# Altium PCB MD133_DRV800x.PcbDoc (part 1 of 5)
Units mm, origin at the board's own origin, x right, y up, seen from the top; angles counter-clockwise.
Board outline 152.66 x 101.89 mm, 4 copper layers (Top Layer, Mid-Layer 1, Mid-Layer 2, Bottom Layer), stack 2.355 mm thick; 306 components, 166 nets, 1010 pads, 1623 vias.
Unrouted connection lines stored in the file: 4.
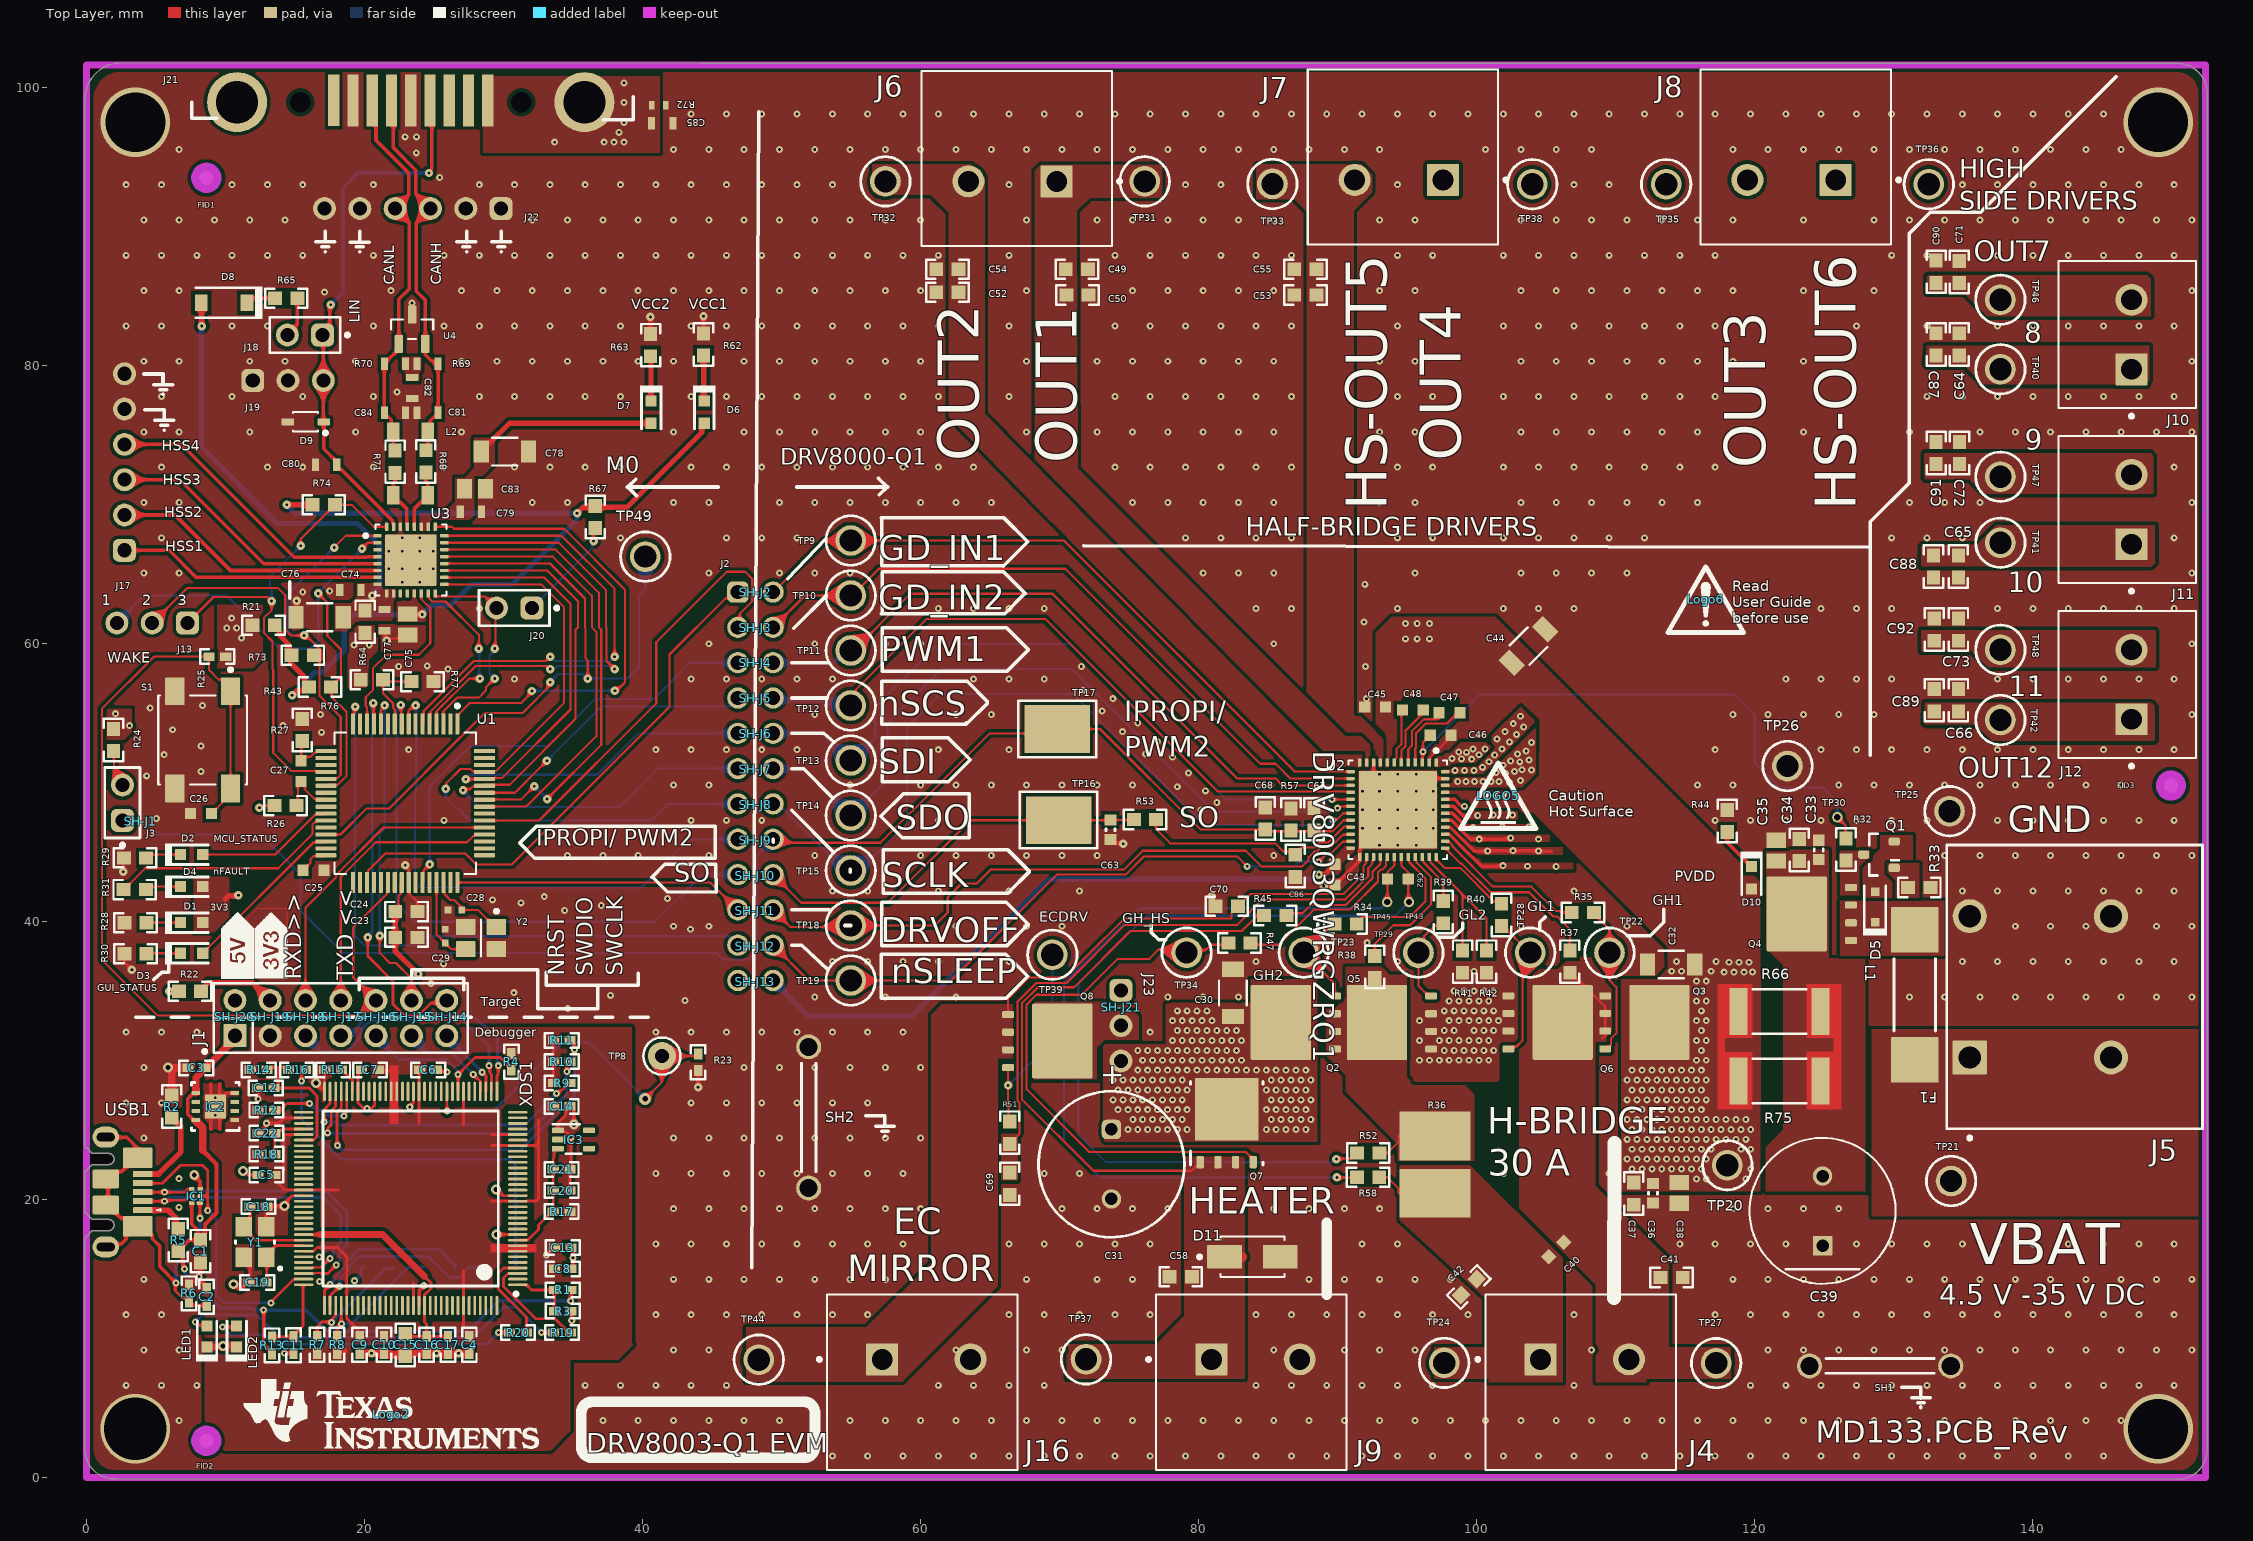
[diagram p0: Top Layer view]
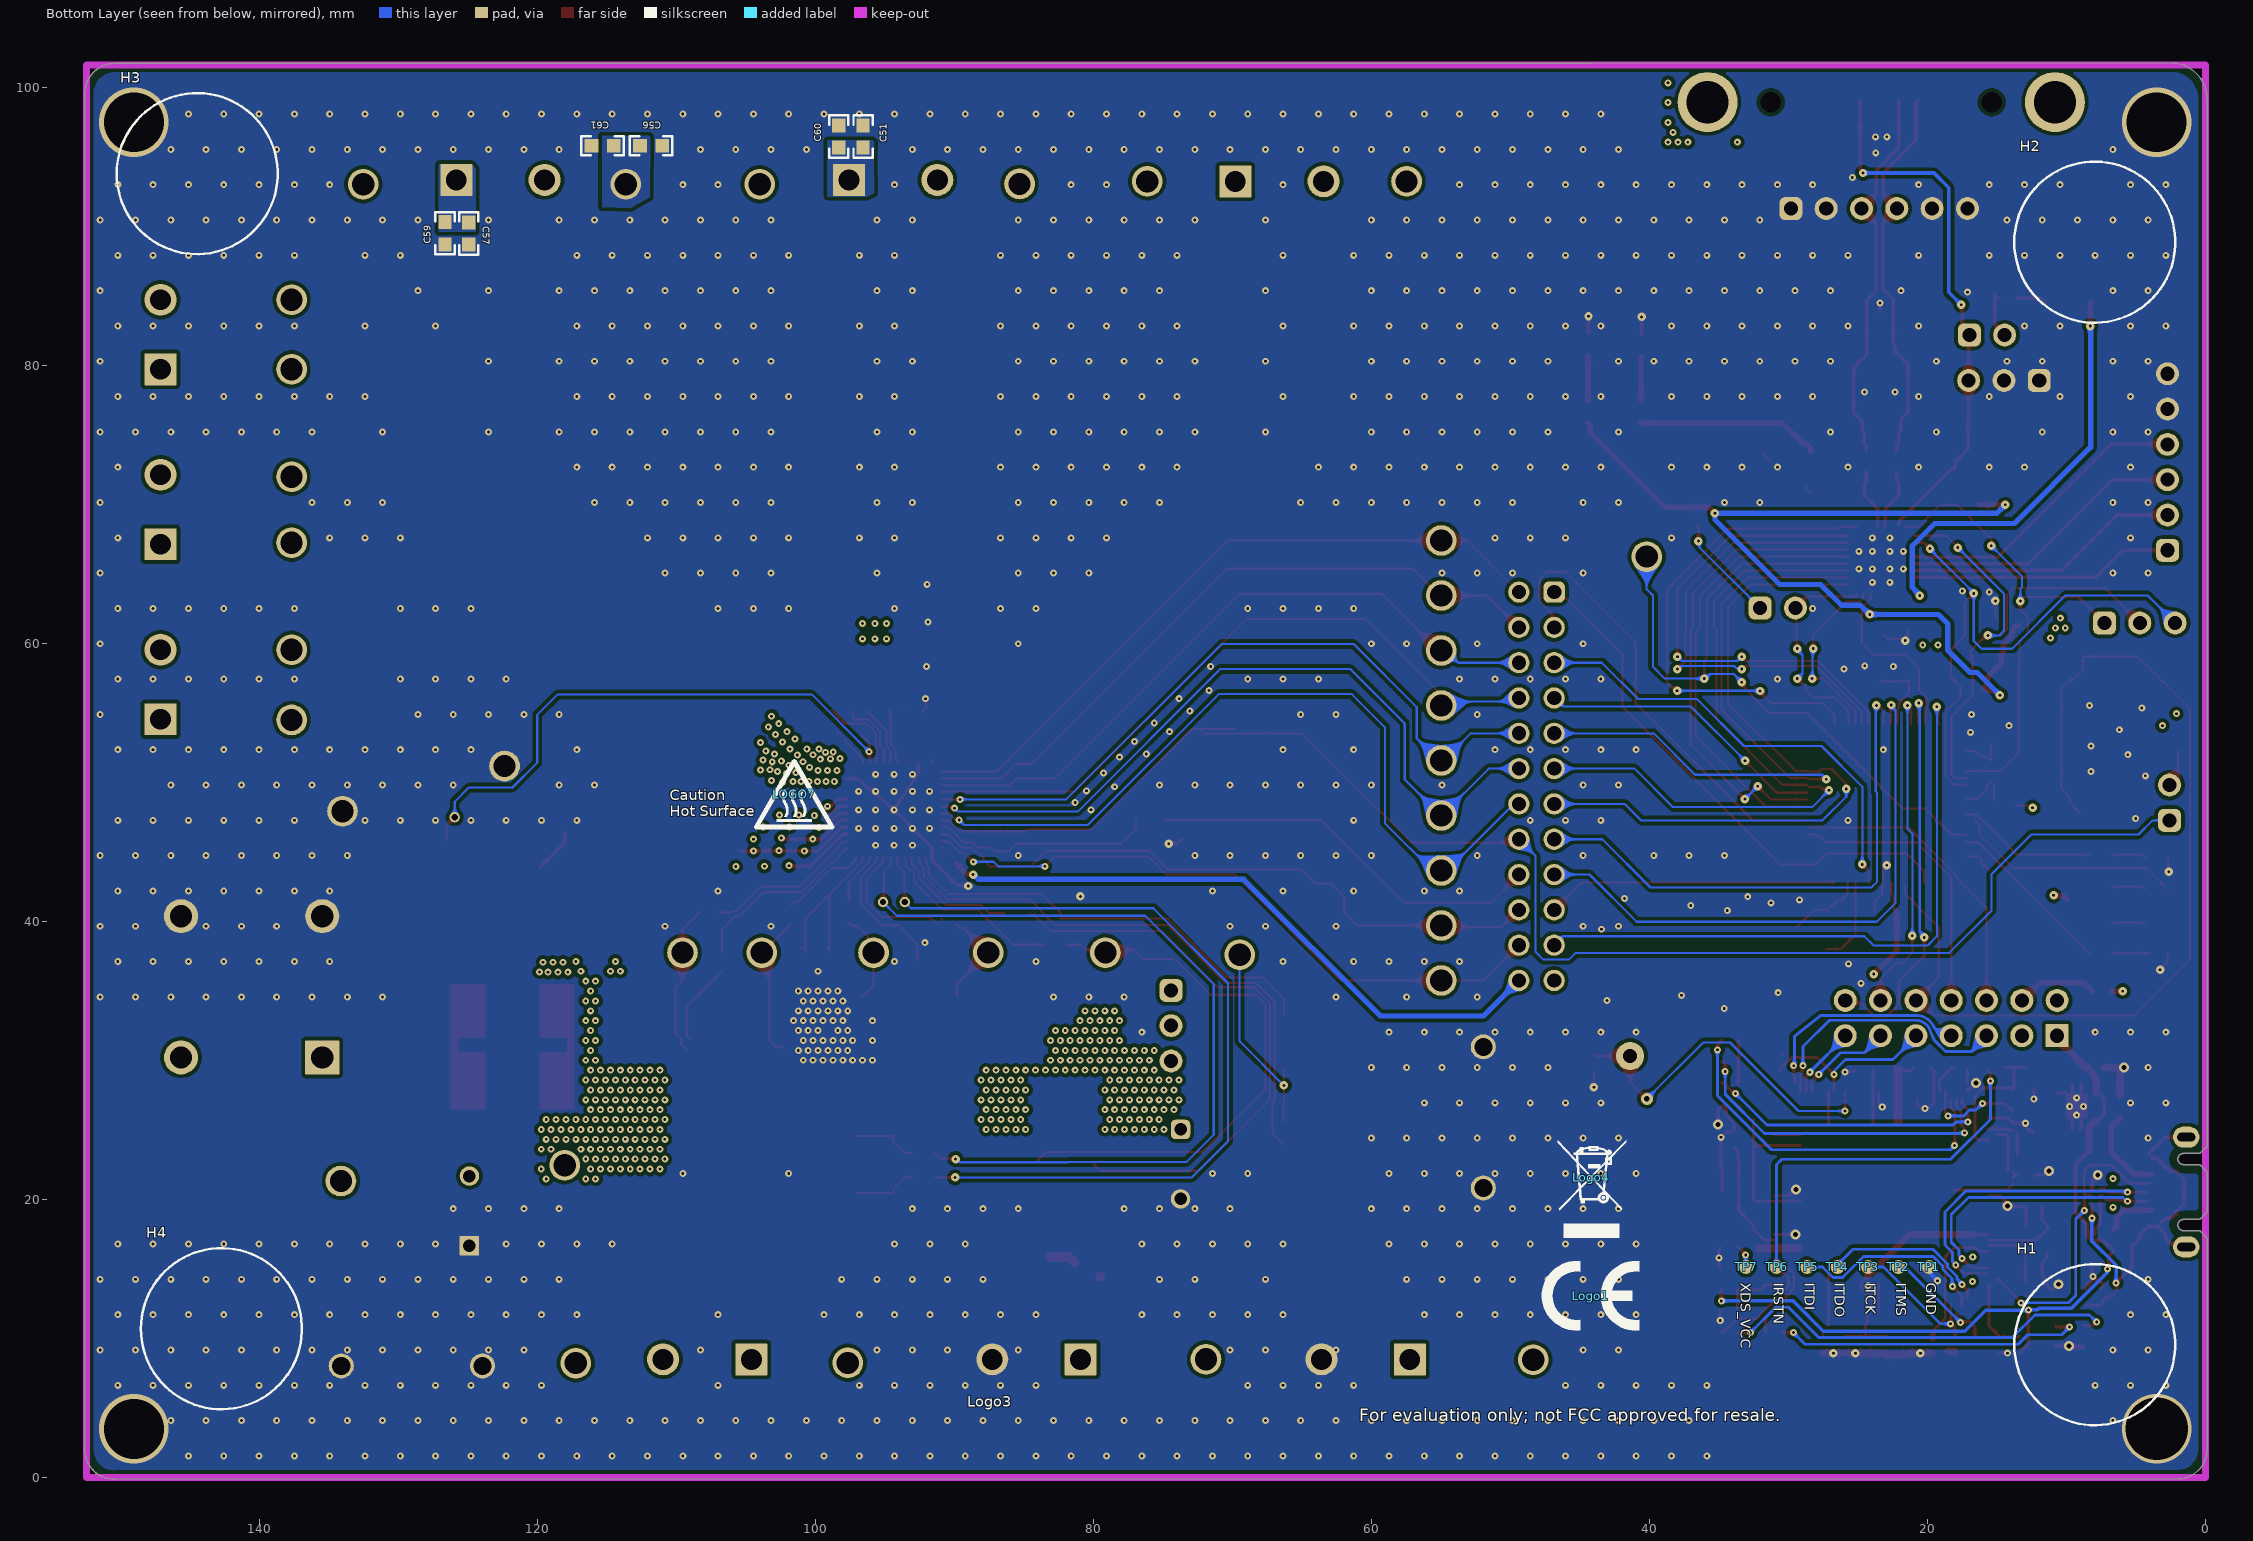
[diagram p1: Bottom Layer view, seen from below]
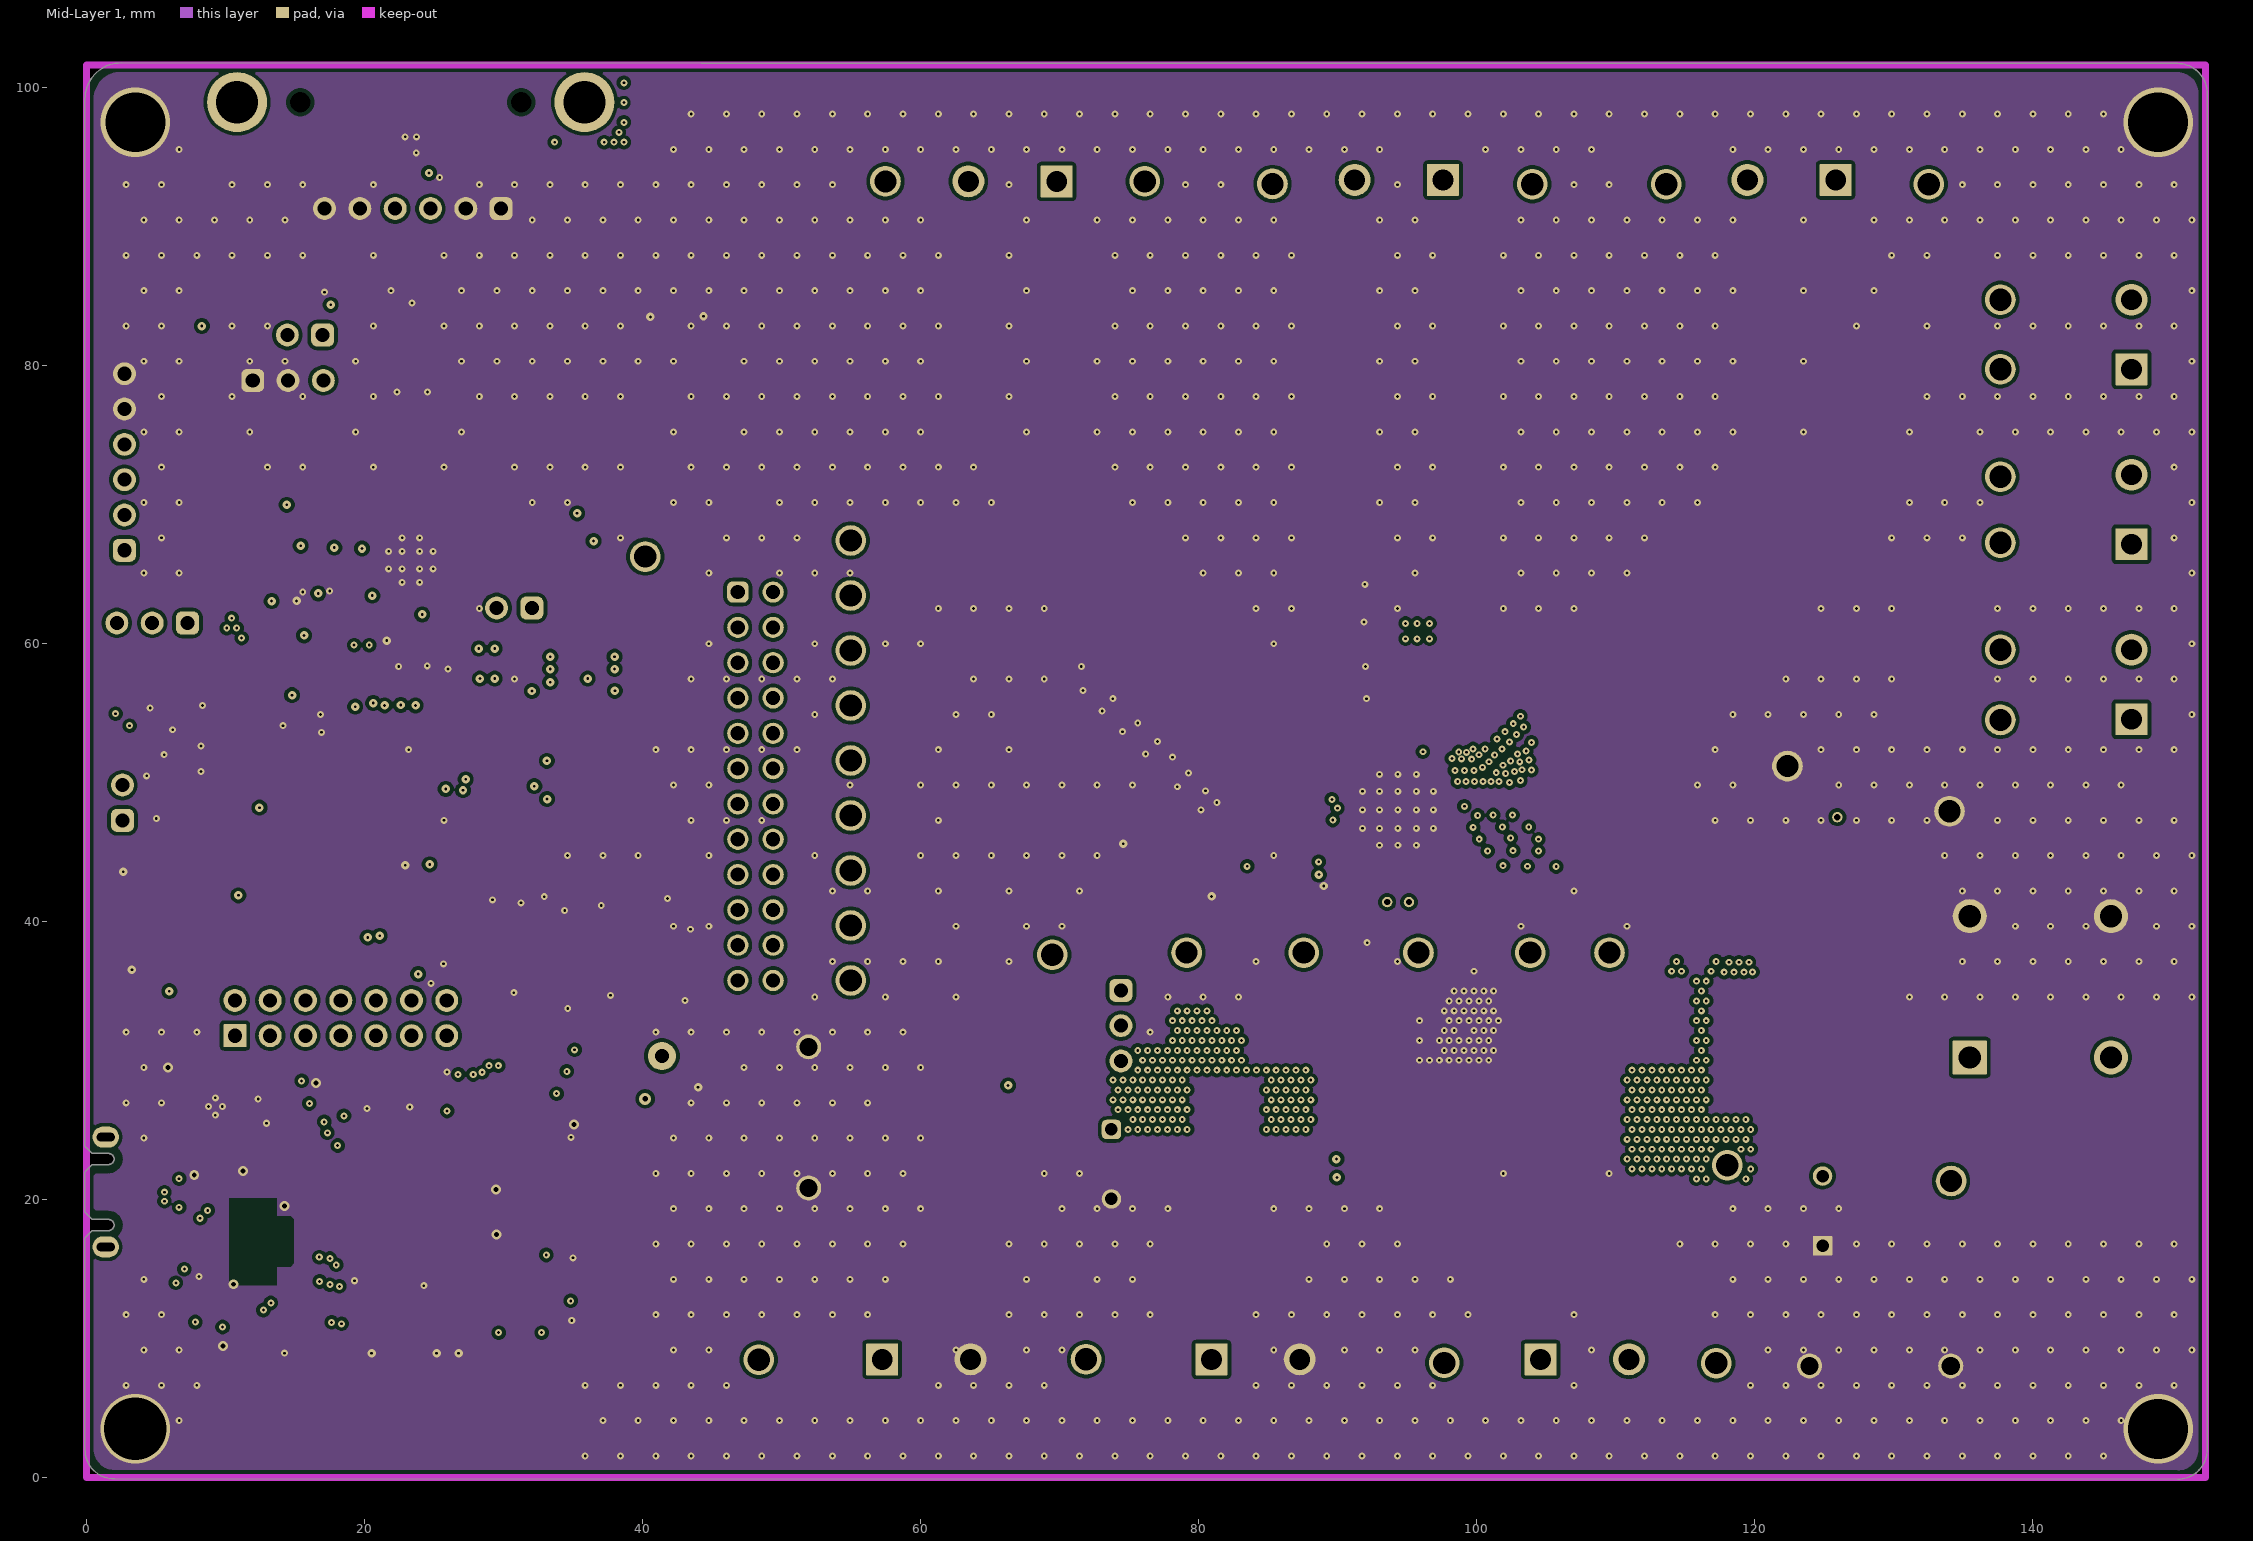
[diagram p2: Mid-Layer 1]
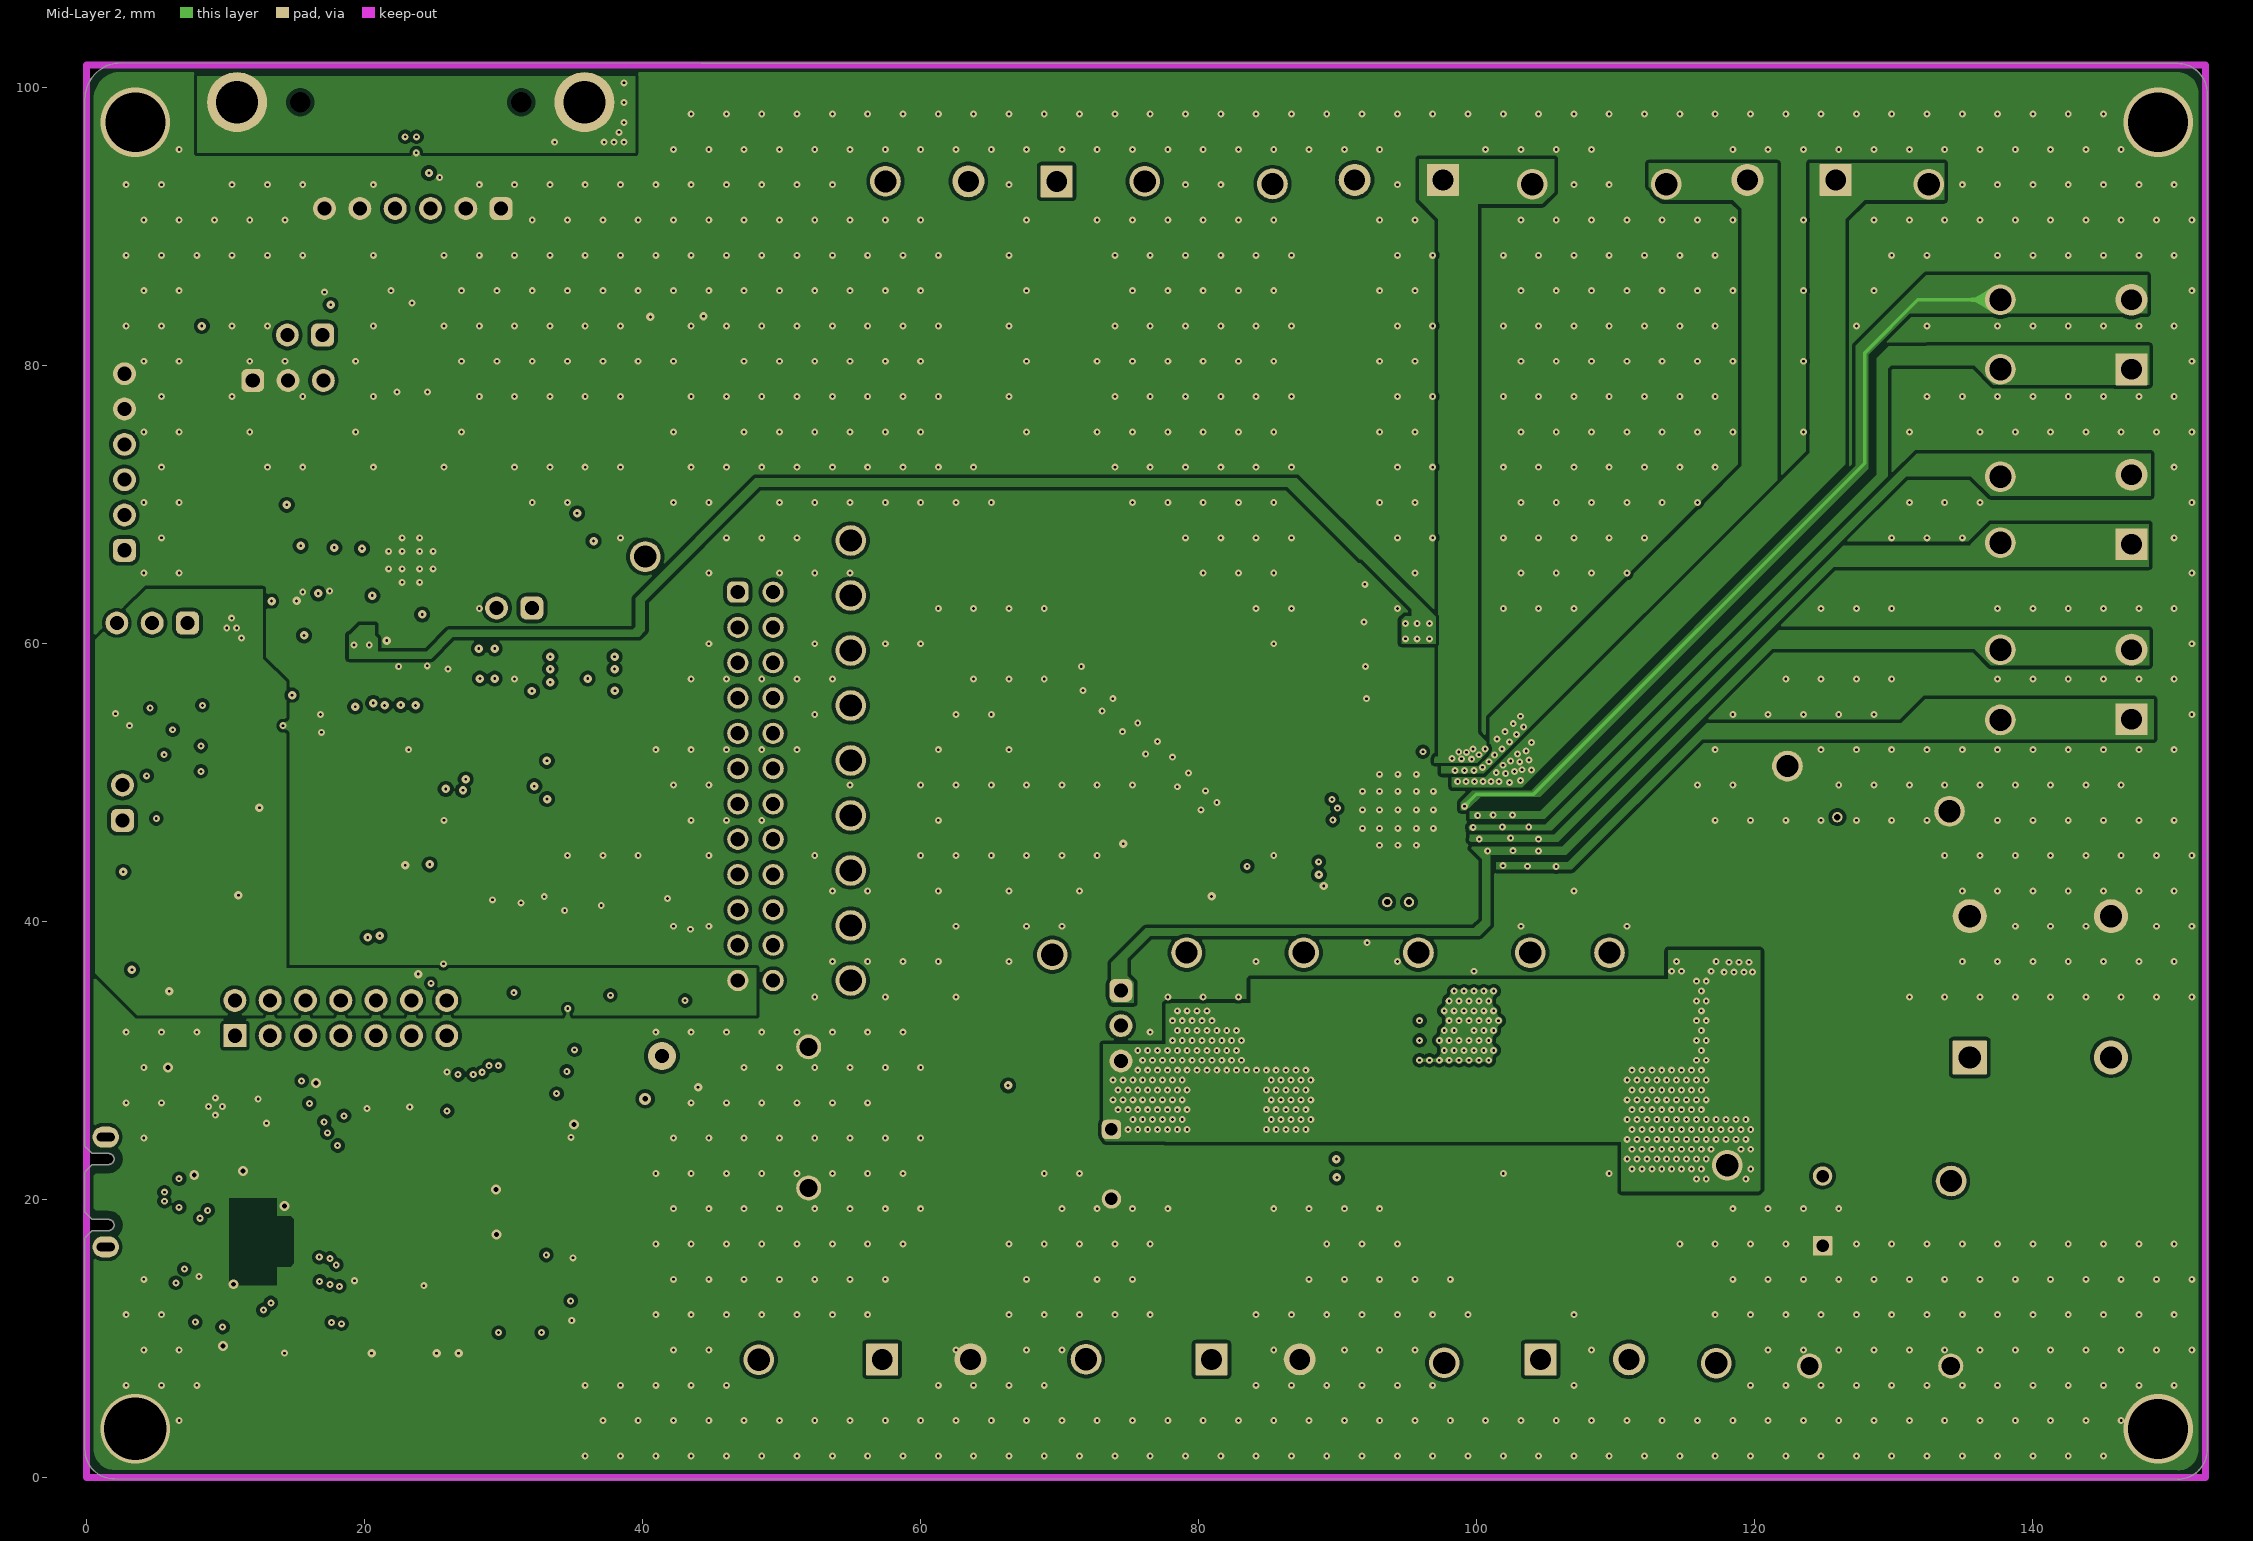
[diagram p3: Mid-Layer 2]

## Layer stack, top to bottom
Top Solder: solder mask 0.0102, Solder Resist, Dk 3.5
Top Layer: signal copper 0.07
Dielectric1: core 1.5037, FR-4 High Tg, Dk 4.8
Mid-Layer 1: signal copper 0.0356
Dielectric2: dielectric 0.32, FR-4, Dk 4.8
Mid-Layer 2: signal copper 0.0356
Dielectric3: dielectric 0.32, FR-4, Dk 4.8
Bottom Layer: signal copper 0.07
Bottom Solder: solder mask 0.0102, Solder Resist, Dk 3.5

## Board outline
-0.127,2.032 -0.127,15.278 -0.13,15.295 -0.13,17.22 -0.116,17.256 0.384,17.756 0.42,17.77 1.57,17.77 ccw(c1.57,18.17) 1.97,18.17 ccw(c1.57,18.17) 1.57,18.57 0.42,18.57 0.384,18.584 -0.116,19.084 -0.13,19.12 -0.13,21.97 -0.116,22.006 0.384,22.506 0.42,22.52 1.57,22.52 ccw(c1.57,22.92) 1.97,22.92 ccw(c1.57,22.92) 1.57,23.32 0.42,23.32 0.384,23.334 -0.009,23.728 cw(c0,23.855) -0.127,23.853 -0.13,23.87 -0.13,25.795 -0.127,25.812 -0.127,91.1 -0.127,99.168 cw(c2.471,99.168) 2.471,101.766 44.195,101.727 150.4,101.727 cw(c150.4,99.6) 152.527,99.6 152.527,2 cw(c150.4,2) 150.4,-0.127 2,-0.095 cw(c2,2.032)

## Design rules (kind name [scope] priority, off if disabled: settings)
AcuteAngle [All] p1: minimum=4.50000000000000E+0001 checktracksonly=FALSE
AssemblyTestPointUsage [All] p1: valid=2
BoardOutlineClearance BoardOutlineClearance_MountingHoles [OnCopper and InComponentClass('Mounting Holes')] p1: gap=0.381 ignorepadtopadclearanceinfootprint=FALSE
BoardOutlineClearance BoardOutlineClearance_Poly [OnCopper and IsPoly] p2: gap=0.635 ignorepadtopadclearanceinfootprint=FALSE
BoardOutlineClearance [OnCopper and Not InComponentClass('Logo') and not InComponentClass('FiducialMark') and not InRegion(1000,500,4000,800) and not InPoly] p3: gap=0.381 ignorepadtopadclearanceinfootprint=FALSE
Clearance Clearance_Keepouts [((IsTrack Or IsArc) And Not InPoly) And IsFree and IsKeepOut vs ((IsTrack Or IsArc) And Not InPoly) And IsFree and IsKeepOut] p1: gap=0 ignorepadtopadclearanceinfootprint=FALSE
Clearance Clearance_Poly [InPolygon] p2: gap=0.254 ignorepadtopadclearanceinfootprint=TRUE
Clearance Clearance_FiducialMark [IsKeepOut and InComponentClass('FiducialMark') vs IsPad and InComponentClass('FiducialMark')] p3: gap=0 ignorepadtopadclearanceinfootprint=TRUE
Clearance [All] p4: gap=0.152 ignorepadtopadclearanceinfootprint=TRUE
ComponentClearance ComponentClearance_PI_FILTER_R75 [InComponent('R75') vs InComponent('L1')] p1: gap=0 collisioncheckmode=3 verticalgap=0 showdistances=FALSE
ComponentClearance ComponentClearance_PI_FILTER_R66 [InComponent('R66') vs InComponent('L1')] p2: gap=0 collisioncheckmode=3 verticalgap=0 showdistances=FALSE
ComponentClearance ComponentClearance_CANL_Choke [InComponent('L2') vs InComponent('R71')] p3: gap=0 collisioncheckmode=3 verticalgap=0 showdistances=FALSE
ComponentClearance ComponentClearance_CANH_Choke [InComponent('L2') vs InComponent('R68')] p4: gap=0 collisioncheckmode=3 verticalgap=0 showdistances=FALSE
ComponentClearance ComponentClearance_MountingHoles_FiducialMarks [InComponentClass('Mounting Holes') vs InComponentClass('FiducialMark')] p5: gap=1.27 collisioncheckmode=3 verticalgap=0.254 showdistances=FALSE
ComponentClearance ComponentClearance_Shunt [InComponentClass('Header') vs InComponentClass('Shunt')] p6: gap=0 collisioncheckmode=3 verticalgap=0 showdistances=FALSE
ComponentClearance ComponentClearance_Logo [InComponentClass('Logo')] p7: gap=0.762 collisioncheckmode=3 verticalgap=0.254 showdistances=FALSE
ComponentClearance ComponentClearance_ScrewToNut [(HasFootprint('NY PMS 440 0025 PH')) vs (HasFootprint('Keystone_1902C'))] p8: gap=0.127 collisioncheckmode=3 verticalgap=0.254 showdistances=FALSE
ComponentClearance ComponentClearance_MountingHoles [InComponentClass('Mounting Holes')] p9: gap=2.54 collisioncheckmode=3 verticalgap=2540 showdistances=FALSE
ComponentClearance ComponentClearance_SmallPassives [HasFootprint('0201*') or HasFootprint('0402*') or HasFootprint('0508') or HasFootprint('0603*') or HasFootprint('0612') or HasFootprint('0805*') or HasFootprint('0815*') or HasFootprint('0830*') or HasFootprint('1206*') or HasFootprint('1210*') or HasFootprint('1808*') or HasFootprint('1812*') or HasFootprint('1825*') or HasFootprint('2010*') or HasFootprint('2220*') or HasFootprint('2225*') or HasFootprint('2512*') or HasFootprint('2728*') or HasFootprint('3518*') vs HasFootprint('0201*') or HasFootprint('0402*') or HasFootprint('0508') or HasFootprint('0603*') or HasFootprint('0612') or HasFootprint('0805*') or HasFootprint('0815*') or HasFootprint('0830*') or HasFootprint('1206*') or HasFootprint('1210*') or HasFootprint('1808*') or HasFootprint('1812*') or HasFootprint('1825*') or HasFootprint('2010*') or HasFootprint('2220*') or HasFootprint('2225*') or HasFootprint('2512*') or HasFootprint('2728*') or HasFootprint('3518*')] p10: gap=0.38 collisioncheckmode=3 verticalgap=0.254 showdistances=FALSE
ComponentClearance ComponentClearance_THtoSMT [IsThruComponent vs IsSMTComponent] p11: gap=0.762 collisioncheckmode=3 verticalgap=0.762 showdistances=FALSE
ComponentClearance ComponentClearance_THtoTH [IsThruComponent vs IsThruComponent] p12: gap=0.508 collisioncheckmode=3 verticalgap=0.762 showdistances=FALSE
ComponentClearance [All] p13: gap=0.508 collisioncheckmode=3 verticalgap=0.254 showdistances=FALSE
DiffPairsRouting [All] p1: maxlimit=2.54 minlimit=0.254 mostfreqgap=0.254 toplayer_minwidth=0.152 toplayer_maxwidth=0.381 toplayer_prefwidth=0.254 midlayer1_minwidth=0.152 midlayer1_maxwidth=0.381 midlayer1_prefwidth=0.254 midlayer2_minwidth=0.152 midlayer2_maxwidth=0.381 midlayer2_prefwidth=0.254 bottomlayer_minwidth=0.152 bottomlayer_maxwidth=0.381 bottomlayer_prefwidth=0.254 maxuncoupledlength=25.4
FabricationTestPointUsage TestPointUsage [All] p1: valid=2 allowmultiple=FALSE
FabricationTestpoint Testpoint [All] p1: side=3 testpointundercomponent=TRUE minsize=1.016 maxsize=2.54 preferedsize=1.524 minholesize=0 maxholesize=1.016 preferedholesize=0.813 testpointgrid=0.025 allowsidetop=TRUE allowsidebottom=TRUE usegrid=TRUE gridtolerance=0
FanoutControl Fanout_LCC [IsLCC] p1: bgadir=Out bgaviamode=Centered fanoutstyle=Auto fanoutdirection=Alternating viagrid=0.025 // Fanout_LCC (Default Rule)
FanoutControl Fanout_BGA [IsBGA] p2: bgadir=Out bgaviamode=Centered fanoutstyle=Auto fanoutdirection=Alternating viagrid=0.025 // Fanout_BGA (Default Rule)
FanoutControl Fanout_Default [All] p4: bgadir=Out bgaviamode=Centered fanoutstyle=Auto fanoutdirection=Alternating viagrid=0.025 // Fanout_Default (Default Rule)
FanoutControl Fanout_Small [(CompPinCount < 5)] p5: bgadir=Out bgaviamode=Centered fanoutstyle=Auto fanoutdirection=OutThenIn viagrid=0.025 // Fanout_Small (Default Rule)
HoleSize [All] p1: absolutevalues=TRUE maxlimit=6.375 minlimit=0.2 maxpercent=80.000 minpercent=20.000
MinimumAnnularRing MinimumAnnularRing_ThermalPadVias [IsVia and InAnyComponent] p1: minimumring=0.15
MinimumAnnularRing [All] p2: minimumring=0.15
MinimumSolderMaskSliver MinimumSolderMaskSliver_Logo [InComponentClass('Logo') vs InComponentClass('Logo')] p1: minsoldermaskwidth=0.018
MinimumSolderMaskSliver [All] p2: minsoldermaskwidth=0.1
PlaneClearance [All] p1: clearance=0.254
PlaneConnect [All] p1: planeconnectstyle=Direct reliefexpansion=0.254 reliefentries=4 reliefconductorwidth=0.254 reliefairgap=0.254
PolygonConnect [All] p1: connectstyle=Direct reliefconductorwidth=0.254 reliefentries=4 polygonreliefangle="90 Angle" airgapwidth=0.254
RoutingVias ThermalPadVias [IsVia and InAnyComponent] p1: holewidth=0.2 width=0.5 viastyle="Through Hole" minholewidth=0.2 minwidth=0.5 maxholewidth=0.33 maxwidth=0.6
RoutingVias [All] p2: holewidth=0.406 width=0.864 viastyle="Through Hole" minholewidth=0.2 minwidth=0.5 maxholewidth=6 maxwidth=6
SilkToBoardRegionClearance [Not ((IsComment or IsDesignator) And (Hide <> 'False')) and not InRegion(1000,500,4000,800)] p1:
SilkToSilkClearance SilkToSilkClearance_Pb-FreeLogo [(HasFootprint('Pb-Free_Overlay_Medium') OR HasFootprint('Pb-Free_Overlay_Small')) vs (HasFootprint('Pb-Free_Overlay_Medium') OR HasFootprint('Pb-Free_Overlay_Small'))] p1: silktosilkclearance=0
SilkToSilkClearance [All] p2: silktosilkclearance=0.1
SilkToSolderMaskClearance SilkToComponentPadClearance [(IsPad or IsFill or IsRegion) and InAnycomponent] p1: minsilkscreentomaskgap=0.127 clearancetoexposedcopper=TRUE
SilkToSolderMaskClearance "Silk to Solder Mask Opening" [All] p2: minsilkscreentomaskgap=0.1 clearancetoexposedcopper=FALSE
SolderMaskExpansion [All] p1: expansion=0.05 istentingtop=FALSE
UnRoutedNet [All] p1: checkbadconnections=TRUE
Width [All] p1: maxlimit=2.54 minlimit=0.152 preferedwidth=0.254 checkconnectedcopper=TRUE
13 further rules are at their usual default settings.

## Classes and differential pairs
component class MD133_Hardware: !PCB1 FID1 FID2 FID3 H1 H2 H3 H4 Logo1 Logo2 Logo3 Logo4 LOGO5 Logo6 LOGO7 ZZ1 ZZ2 ZZ3 ZZ4
component class MD133_TCAN284x: C74 C75 C76 C77 C78 C79 C80 C81 C82 C83 C84 C85 D6 D7 D8 D9 J13 J17 J18 J19 J20 J21 J22 L2 R43 R62 R63 R64 R65 R67 R68 R69 R70 R71 R72 R73 R74 U3 U4
component class MD133_DRV800x: 15 C30 C31 C32 C33 C34 C35 C36 C37 C38 C39 C40 C41 C42 C43 C44 C45 C46 C47 C48 C49 C50 C51 C52 C53 C54 C55 C56 C57 C58 C59 C60 C61 C62 C63 C64 C65 C66 C67 C68 C69 C70 C71 C72 C73 C86 C87 C88 C89 C90 C91 C92 D5 D11 F1 J4 J5 J6 J7 J8 J9 J10 J11 J12 J16 J23 L1 L? Q1 Q2 Q3 Q4 Q5 Q6 Q7 Q8 R32 R33 R34 R35 R36 R37 R38 R39 R40 R41 R42 R45 R47 R51 R52 R53 R57 R58 R66 R75 SH1 SH2 SH-J21 TP20 TP21 TP22 TP23 TP24 TP25 TP26 TP27 TP28 TP29 TP30 TP31 TP32 TP33 TP34 TP35 TP36 TP37 TP38 TP39 TP40 TP41 TP42 TP43 TP44 TP45 TP46 TP47 TP48 U2
component class MD133_XDS110: C1 C2 C3 C4 C5 C6 C7 C8 C9 C10 C11 C12 C13 C14 C15 C16 C17 C18 C19 C20 C21 C22 IC1 IC2 IC3 J1 LED1 LED2 R1 R2 R3 R4 R5 R6 R7 R8 R9 R10 R11 R12 R13 R14 R15 R16 R17 R18 R19 R20 SH-J14 SH-J15 SH-J16 SH-J17 SH-J18 SH-J19 SH-J20 TP1 TP2 TP3 TP4 TP5 TP6 TP7 USB1 XDS1 Y1
component class MD133_M0: 20 C23 C24 C25 C26 C27 C28 C29 D1 D2 D3 D4 D10 J2 J3 R21 R22 R23 R24 R25 R26 R27 R28 R29 R30 R31 R44 R76 R77 S1 SH-J1 SH-J2 SH-J3 SH-J4 SH-J5 SH-J6 SH-J7 SH-J8 SH-J9 SH-J10 SH-J11 SH-J12 SH-J13 TP8 TP9 TP10 TP11 TP12 TP13 TP14 TP15 TP16 TP17 TP18 TP19 TP49 U1 Y2
differential pair S: +S_P -S_N
differential pair SNS: +SNS_P -SNS_N
differential pair XDS_USB_D: +XDS_USB_D_P -XDS_USB_D_N

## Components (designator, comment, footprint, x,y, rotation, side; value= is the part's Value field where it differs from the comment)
C1 "C0603C225K8PACTU" 0603 8.182,16.288 r270 top value=2.2uF
C2 "GRM155R71H332KA01D" 0402 8.626,13.003 r90 top value=3300pF
C3 "C1005X5R1E105K050BC" 0402 7.89,29.482 r180 top value=1uF
C4 "CL05A225KQ5NNNC" 0402 27.519,9.549 r270 top value=2.2uF
C5 "GRM155R71E103KA01D" 0402 12.929,21.772 r180 top value=0.01uF
C6 "GRM155R71E103KA01D" 0402 24.557,29.336 r0 top value=0.01uF
C7 "GRM155R71E103KA01D" 0402 20.38,29.336 r180 top value=0.01uF
C8 "GRM155R70J104KA01D" 0402 34.244,15.022 r0 top value=0.1uF
C9 "GRM155R70J104KA01D" 0402 19.637,9.549 r270 top value=0.1uF
C10 "C1005X5R1E105K050BC" 0402 21.387,9.549 r270 top value=1uF
C11 "GRM155R70J104KA01D" 0402 14.88,9.535 r270 top value=0.1uF
C12 "GRM155R70J104KA01D" 0402 12.873,28.03 r180 top value=0.1uF
C13 "C1005X5R1E105K050BC" 0402 34.244,16.545 r0 top value=1uF
C14 "GRM155R71E103KA01D" 0402 34.156,26.709 r0 top value=0.01uF
C15 "C0603C225K8PACTU" 0603 22.919,9.549 r270 top value=2.2uF
C16 "GRM155R70J104KA01D" 0402 24.452,9.549 r270 top value=0.1uF
C17 "C1005X5R1E105K050BC" 0402 25.985,9.549 r270 top value=1uF
C18 "GRM1555C1H120JA01D" 0402 12.353,19.488 r0 top value=12pF
C19 "GRM1555C1H120JA01D" 0402 12.279,14.042 r180 top value=12pF
C20 "GRM155R71E103KA01D" 0402 34.156,20.651 r0 top value=0.01uF
C21 "GRM155R70J104KA01D" 0402 34.156,22.174 r0 top value=0.1uF
C22 "GRM155R70J104KA01D" 0402 12.929,24.78 r180 top value=0.1uF
C23 "GRM188R61E106KA73D" 0603 22.995,38.862 r0 top value=10uF
C24 "885012206095" 0603 22.995,40.714 r0 top value=0.1uF
C25 "885012206075R" WCAP-CSGP_0603_L1.6W0.8H0.8_Reflow 16.308,43.688 r180 top value=470nF
C26 "885012206065" WCAP-CSGP_0603_L1.6W0.8H0.8_Reflow 8.23,47.764 r0 top value=10nF
C27 "885012206126" WCAP-CSGP_0603_L1.6W0.8H0.8_Reflow 15.428,50.814 r270 top value=1µF
C28 "885012005057" WCAP-CSGP_0402_L1W0.5H0.5 26.477,40.841 r0 top value=22pF
C29 "885012005057" WCAP-CSGP_0402_L1W0.5H0.5 25.793,38.948 r270 top value=22pF
C30 "CC1206KKX7R0BB105" 1206_180 82.451,34.865 r270 top value=1uF
C31 "860020675020" WCAP-ATG5_D10H12.5 73.713,22.544 r90 top value=220µF
C32 "CC1206KKX7R0BB105" 1206_180 113.968,36.912 r0 top value=1uF
C33 "885012206089" 0603L 124.595,45.151 r90 top value=0.01uF
C34 "885012206095" 0603 123.189,45.151 r90 top value=0.1uF
C35 "885012207103" 0805L 121.547,45.101 r90 top value=1uF
C36 "885012206089" 0603L 112.674,20.453 r270 top value=0.01uF
C37 "885012206095" 0603 111.277,20.428 r270 top value=0.1uF
C38 "885012207103" 0805L 114.554,20.478 r270 top value=1uF
C39 "860020675021" FP-860020675021_RADIAL-MFG 124.866,19.192 r90 top
C40 "885012206120" WCAP-CSGP_0603_L1.6W0.8H0.8_Reflow 105.702,16.408 r45 top
C41 "885012206091" 0603 114.008,14.402 r180 top value=0.022uF
C42 "885012206091" 0603 99.425,13.709 r45 top value=0.022uF
C43 "885012206076" WCAP-CSGP_0603_L1.6W0.8H0.8_Reflow 89.798,43.373 r90 top value=1µF
C44 "885012108022" 1206_180 103.718,59.813 r45 top value=10uF
C45 "885012206120" WCAP-CSGP_0603_L1.6W0.8H0.8_Reflow 92.688,55.421 r0 top value=100nF
C46 "885012206076" WCAP-CSGP_0603_L1.6W0.8H0.8_Reflow 97.397,53.405 r0 top value=1µF
C47 "885012206120" WCAP-CSGP_0603_L1.6W0.8H0.8_Reflow 98.03,55.021 r0 top value=100nF
C48 "885012206120" WCAP-CSGP_0603_L1.6W0.8H0.8_Reflow 95.39,55.223 r0 top value=100nF
C49 "885012206091" 0603 71.227,86.919 r180 top value=0.022uF
C50 "885012206091" 0603 71.266,85.073 r180 top value=0.022uF
C51 "885012206091" 0603 98.298,96.47 r270 bottom value=0.022uF
C52 "885012206091" 0603 61.913,85.268 r0 top value=0.022uF
C53 "885012206091" 0603 87.665,85.073 r0 top value=0.022uF
C54 "885012206091" 0603 61.913,86.919 r0 top value=0.022uF
C55 "885012206091" 0603 87.665,86.919 r0 top value=0.022uF
C56 "885012206091" 0603 111.796,95.806 r0 bottom value=0.022uF
C57 "885012206091" 0603 124.917,89.496 r90 bottom value=0.022uF
C58 "885012206091" 0603 78.702,14.453 r0 top value=0.022uF
C59 "885012206091" 0603 126.619,89.516 r90 bottom value=0.022uF
C60 "885012206091" 0603 96.549,96.47 r270 bottom value=0.022uF
C61 "885012206091" 0603 115.286,95.806 r180 bottom value=0.022uF
C62 "885012206090" FP-885012206090_0603-MFG 94.315,43.059 r180 top
C63 "885012206040" 0603L 73.636,46.6 r270 top value=0.01uF
C64 "885012206091" 0603 134.696,81.52 r270 top value=0.022uF
C65 "885012206091" 0603 134.636,65.545 r90 top value=0.022uF
C66 "885012206091" 0603 134.636,55.922 r270 top value=0.022uF
C67 "C0603C512J5GAC7867" 0603 88.281,47.359 r90 top value=5100pF
C68 "885012206114" 0603 84.771,47.409 r90 top value=0.01uF
C69 "C0603C512J5GAC7867" 0603 66.391,21.139 r270 top value=5100pF
C70 "885012206022" 0603 82.007,41.102 r180 top value=0.22uF
C71 "885012206091" 0603 134.696,86.728 r270 top value=0.022uF
C72 "885012206091" 0603 134.722,73.703 r270 top value=0.022uF
C73 "885012206091" 0603 134.636,60.998 r270 top value=0.022uF
C74 "C1608X7R1H104K080AA" 0603S 18.966,63.853 r180 top value=0.1uF
C75 "CGA4J3X7R1C475K125AE" 0805L 23.108,61.368 r270 top value=4.7uF
C76 "CL31B106KBHNNNE" 1206_180 16.758,61.893 r180 top value=10uF
C77 "C1608X7R1H104K080AA" 0603S 21.426,61.681 r270 top value=0.1uF
C78 "CL31B106KBHNNNE" 1206_180 30.078,73.809 r0 top value=10uF
C79 "C1608X7R1H104K080AA" 0603S 27.631,69.477 r0 top value=0.1uF
C80 "06035A221FAT2A" 0603S 17.226,72.859 r180 top value=220pF
C81 "GRM1885C2A200JA01D" 0603S 24.513,76.608 r180 top value=20pF
C82 "06031C472KAT2A" 0603S 23.406,78.371 r90 top value=4700pF
C83 "CGA4J3X7R1C475K125AE" 0805L 27.931,71.131 r0 top value=4.7uF
C84 "GRM1885C2A200JA01D" 0603S 22.169,76.608 r180 top value=20pF
C85 "C0603X103K1RACTU" 0603S 41.404,97.438 r0 top value=0.01uF
C86 "885012206095" 0603 86.937,44.002 r270 top value=0.1uF
C87 "885012206091" 0603 133.036,81.52 r270 top value=0.022uF
C88 "885012206091" 0603 132.846,65.545 r90 top value=0.022uF
C89 "885012206091" 0603 132.898,55.922 r270 top value=0.022uF
C90 "885012206091" 0603 133.036,86.746 r270 top value=0.022uF
C91 "885012206091" 0603 133.036,73.703 r270 top value=0.022uF
C92 "885012206091" 0603 132.898,60.998 r270 top value=0.022uF
D1 "150060VS75000" WL-SMCW_GREEN 7.545,39.921 r0 top value=Green
D2 "150060VS75000" WL-SMCW_GREEN 7.545,44.812 r0 top value=Green
D3 "150060VS75000" WL-SMCW_GREEN 7.545,37.724 r0 top value=Green
D4 "150060RS75000" WL-SMCW_RED 7.545,42.511 r0 top value=Red
D5 "1N4148WS-7-F" SOD-323 128.649,41.048 r90 top value=75V
D6 "150060VS75000" WL-SMCW_GREEN 44.42,76.647 r270 top value=Green
D7 "150060VS75000" WL-SMCW_GREEN 40.604,76.647 r270 top value=Green
D8 "1N4148W-TP" SOD-123 9.886,84.513 r180 top value=100V
D9 "ESD1LIN24DYFR" DYF0002A-MFG 15.752,75.947 r180 top
D10 "150060VS75000" WL-SMCW_GREEN 119.748,43.151 r270 top value=Green
D11 "B340AE-13" FP-B340AE-13_SMA-MFG 83.853,15.878 r0 top
F1 "0463030.ER" Fuse_0463 131.498,34.729 r270 top
FID1 "Fiducial" Fiducial10-20 8.605,93.498 r0 top
FID2 "Fiducial" Fiducial10-20 8.605,2.652 r0 top
FID3 "Fiducial" Fiducial10-20 149.926,49.784 r0 top
H1 "SJ-5303 (CLEAR)" Bumpon_SJ5003Transparent 7.952,9.566 r180 bottom
H2 "SJ-5303 (CLEAR)" Bumpon_SJ5003Transparent 7.952,88.87 r180 bottom
H3 "SJ-5303 (CLEAR)" Bumpon_SJ5003Transparent 144.45,93.802 r180 bottom
H4 "SJ-5303 (CLEAR)" Bumpon_SJ5003Transparent 142.71,10.713 r180 bottom
IC1 "TPD4E004DRYR" DRY0006A 7.864,20.258 r180 top
IC2 "TPS73533DRBT" DRB0008A 9.253,26.696 r180 top
IC3 "LM4040C25IDCKR" DCK0005A_N 35.017,24.322 r0 top
J1 "TSW-107-07-G-D" TSW-107-07-X-D 18.278,33.06 r0 top locked
J2 "TSW-112-08-G-D" Samtec_TSW-112-08-x-D 48.108,49.731 r0 top locked
J3 "TSW-102-07-G-S" TSW-102-07-G-S 2.573,48.55 r90 top
J4 "691250610002" FP-691250610002_CONN_TERM_BLOCK2-MFG 107.464,6.858 r0 top
J5 "691256610002" FP-691256610002_HDR2-MFG 143.002,35.306 r90 top
J6 "691250610002" FP-691250610002_CONN_TERM_BLOCK2-MFG 66.899,94.893 r180 top
J7 "691250610002" FP-691250610002_CONN_TERM_BLOCK2-MFG 94.683,94.996 r180 top
J8 "691250610002" FP-691250610002_CONN_TERM_BLOCK2-MFG 122.936,94.996 r180 top
J9 "691250610002" FP-691250610002_CONN_TERM_BLOCK2-MFG 83.782,6.858 r0 top
J10 "691216710002" FP-691216710002_HDR2-MFG 146.787,82.528 r90 top
J11 "691216710002" FP-691216710002_HDR2-MFG 146.787,69.941 r90 top
J12 "691216710002" FP-691216710002_HDR2-MFG 146.787,57.353 r90 top
J13 "TSW-103-07-G-S" TSW-103-07-G-S 4.709,61.476 r180 top
J16 "691250610002" FP-691250610002_CONN_TERM_BLOCK2-MFG 60.099,6.858 r0 top
J17 "TSW-106-07-G-S" TSW-106-07-G-S 2.715,73.056 r90 top
J18 "TSW-102-07-G-S" TSW-102-07-G-S 15.702,82.192 r180 top
J19 "TSW-103-07-G-S" TSW-103-07-G-S 14.482,78.921 r0 top
J20 "TSW-102-07-G-S" TSW-102-07-G-S 30.756,62.555 r180 top
J21 "190-009-263R001" NORCOMP_190-009-263R001 23.309,101.732 r0 top
J22 "TSW-106-07-G-S" TSW-106-07-G-S 23.459,91.288 r180 top
J23 "TSW-103-07-G-S" TSW-103-07-G-S 74.397,32.512 r270 top
L1 "74439369022" FP-74439369022_IND_SMT_11MM6_10MM5-MFG 121.772,31 r270 top
L2 "ACT45B-101-2P-TL003" ACT45B_NoSilk 23.291,72.944 r90 top value=100uH
LED1 "LTST-C190KRKT" LED_LTST-C190_Red 8.652,10.149 r270 top value=Red
LED2 "LTST-C190GKT" LED_LTST-C190 10.785,10.149 r270 top value=Green
Logo1 "CE Mark" CE_Mark_5mm 44.221,13.08 r180 bottom
Logo2 "Texas Instruments" TI_Stacked_Overlay_Small 21.908,4.572 r0 top
Logo3 "FCC disclaimer" FCC_disclaimer -17.907,49.43 r90 bottom
Logo4 "WEEE logo" WEEE_Minimum 44.166,21.62 r180 bottom
LOGO5 "CAUTION HOT SURFACE" IEC_HotSurface_Small 101.538,49.059 r0 top
Logo6 "CAUTION.  READ USER GUIDE BEFORE USE" IEC_Caution_Small 116.46,63.17 r0 top
LOGO7 "CAUTION HOT SURFACE" IEC_HotSurface_Small 101.5,49.173 r180 bottom
Q1 "BC846BLT1G" SOT-23L 128.924,44.813 r180 top value="65 V"
Q2 "CSD18512Q5B" DNK0008A 86.978,32.734 r180 top value=40V
Q3 "CSD18512Q5B" DNK0008A 112.054,32.75 r0 top value=40V
Q4 "CSD18512Q5B" DNK0008A 124.091,40.548 r180 top value=40V
Q5 "CSD18512Q5B" DNK0008A 93.89,32.734 r180 top value=40V
Q6 "CSD18512Q5B" DNK0008A 105.087,32.75 r0 top value=40V
Q7 "CSD17579Q5A" DQJ0008A 82.006,25.492 r90 top value=30V
Q8 "CSD18512Q5B" DNK0008A 69.1,31.404 r0 top value=40V
R1 "RC0402FR-07330KL" 0402 34.244,13.499 r180 top value=330k
R2 "RC0603JR-070RL" 0603 6.117,26.696 r90 top value=0
R3 "RC0402FR-07220KL" 0402 34.244,11.976 r180 top value=220k
R4 "ERJ-2RKF3301X" 0402 30.545,29.919 r90 top value=3.30k
R5 "RC0603JR-070RL" 0603 6.582,17.088 r270 top value=0
R6 "CRCW04021M00FKED" 0402 7.356,13.248 r270 top value=1.00Meg
R7 "CRCW040210K0JNED" 0402 16.576,9.549 r90 top value=10k
R8 "CRCW040210K0JNED" 0402 18.011,9.549 r90 top value=10k
R9 "CRCW04021K00JNED" 0402 34.168,28.386 r180 top value=1.0k
R10 "CRCW04021K00JNED" 0402 34.168,29.919 r180 top value=1.0k
R11 "CRCW04021K00JNED" 0402 34.168,31.452 r180 top value=1.0k
R12 "CRCW04021K00JNED" 0402 12.929,26.433 r180 top value=1.0k
R13 "CRCW0402100RJNED" 0402 13.327,9.509 r90 top value=100
R14 "CRCW040210K0JNED" 0402 12.367,29.336 r180 top value=10k
R15 "CRCW04024K87FKED" 0402 17.721,29.336 r0 top value=4.87k
R16 "CRCW0402100RJNED" 0402 15.128,29.336 r180 top value=100
R17 "CRCW04021K00JNED" 0402 34.156,19.128 r0 top value=1.0k
R18 "CRCW040251R0JNED" 0402 12.929,23.27 r180 top value=51
R19 "CRCW0402470RJNED" 0402 34.19,10.434 r0 top value=470
R20 "CRCW0402470RJNED" 0402 31.026,10.434 r0 top value=470
R21 "Resistor" 0603 12.723,61.311 r0 top value=0
R22 "Resistor" 0603 7.43,34.992 r180 top value=0
R23 "CRCW040247K0JNED" 0402 43.979,29.886 r90 top value=47k
R24 "RC0603JR-073K3L" 0603 1.927,53.064 r90 top value=3.3k
R25 "CRCW040247K0JNED" 0402 9.398,59.055 r0 top value=47k
R26 "Resistor" 0603 14.296,48.339 r0 top value=0
R27 "Resistor" 0603 15.504,53.779 r270 top value=0
R28 "RC0603JR-07330RL" 0603 3.505,39.921 r0 top value=330
R29 "RC0603JR-07330RL" 0603 3.477,44.582 r0 top value=330
R30 "RC0603JR-07330RL" 0603 3.515,37.689 r0 top value=330
R31 "RC0603JR-07330RL" 0603 3.452,42.296 r0 top value=330
R32 "RC0603JR-0710KL" 0603 126.556,45.183 r270 top value=10k
R33 "RC0603JR-0710KL" 0603 131.826,42.453 r180 top value=10k
R34 "Resistor" 0603 90.559,39.828 r0 top value=0
R35 "Resistor" 0603 107.625,40.648 r180 top value=0
R36 "WSHM28187L000FEA" WSHM2818 97.001,22.523 r90 top value=0.007
R37 "Resistor" 0603 106.689,37.115 r90 top value=0
R38 "Resistor" 0603 92.649,36.733 r90 top value=0
R39 "Resistor" 0603 97.583,40.677 r90 top value=0
R40 "Resistor" 0603 101.773,40.483 r90 top value=0
R41 "Resistor" 0603 98.974,37.115 r90 top value=0
R42 "Resistor" 0603 100.694,37.115 r90 top value=0
R43 "RC0603JR-073K3L" 0603 16.778,56.879 r180 top value=3.3k
R44 "RC0603JR-0716KL" 0603 118.016,47.238 r270 top value=16k
R45 "Resistor" 0603 85.494,40.437 r0 top value=0
R47 "RC0603JR-071KL" 0603 82.921,38.461 r0 top value=1.0k
R51 "RC0603FR-07220RL" 0603 66.391,24.812 r90 top value=220
R52 "RC0603JR-070RL" 0603 92.184,23.353 r0 top value=0
R53 "Resistor" 0603 76.128,47.344 r0 top value=0
R57 "RC0603FR-071KL" 0603 86.63,47.344 r270 top value=1.00k
R58 "RC0603JR-070RL" 0603 92.174,21.614 r0 top value=0
R62 "RC0603JR-07560RL" 0603 44.368,81.511 r270 top value=560
R63 "RC0603JR-07330RL" 0603 40.566,81.461 r270 top value=330
R64 "Resistor" 0603 20.026,61.568 r270 top value=0
R65 "RC0603JR-071KL" 0603 14.353,84.843 r0 top value=1.0k
R66 "HCJ2512ZT0R00" 2512_084 121.771,33.53 r180 top value=0
R67 "RC0603JR-0710KL" 0603 36.575,69.1 r90 top value=10k
R68 "RC0603JR-070RL" 0603 24.398,73.104 r90 top value=0
R69 "RC0603FR-0760R4L" 0603S 24.513,80.125 r0 top value=60.4
R70 "RC0603FR-0760R4L" 0603S 22.169,80.125 r0 top value=60.4
R71 "RC0603JR-070RL" 0603 22.185,73.08 r90 top value=0
R72 "ERJ-2RKF1004X" 0402S 41.148,98.73 r180 top value=1.00Meg
R73 "RC0603JR-073K3L" 0603 15.545,59.151 r180 top value=3.3k
R74 "RC0603JR-073K3L" 0603 17.052,69.977 r180 top value=3.3k
R75 "HCJ2512ZT0R00" 2512_084 121.771,28.525 r180 top value=0
R76 "RC0603JR-0720KL" 0603 20.515,57.4 r180 top value=20k
R77 "RC0603JR-071K8L" 0603 24.16,57.258 r180 top value=1.8k
S1 "430481025816" FP-430481025816_SMT_SW_6MM2_6MM2-MFG 8.344,53.064 r270 top
SH1 "Jumper_2p" Harwin_D3082-05 129.006,8.04 r180 top
SH2 "Jumper_2p" Harwin_D3082-05 51.934,25.908 r90 top
SH-J1 "60900213421" Wurth_60900213421 3.843,47.225 r0 top
SH-J2 "60900213421" Wurth_60900213421 48.075,63.701 r180 top
SH-J3 "60900213421" Wurth_60900213421 48.075,61.152 r180 top
SH-J4 "60900213421" Wurth_60900213421 48.075,58.604 r180 top
SH-J5 "60900213421" Wurth_60900213421 48.075,56.055 r180 top
SH-J6 "60900213421" Wurth_60900213421 48.075,53.507 r180 top
SH-J7 "60900213421" Wurth_60900213421 48.075,50.958 r180 top
SH-J8 "60900213421" Wurth_60900213421 48.075,48.41 r180 top
SH-J9 "60900213421" Wurth_60900213421 48.075,45.861 r180 top
SH-J10 "60900213421" Wurth_60900213421 48.075,43.313 r180 top
SH-J11 "60900213421" Wurth_60900213421 48.075,40.764 r180 top
SH-J12 "60900213421" Wurth_60900213421 48.075,38.216 r180 top
SH-J13 "60900213421" Wurth_60900213421 48.075,35.667 r180 top
SH-J14 "60900213421" Wurth_60900213421 25.974,33.151 r90 top
SH-J15 "60900213421" Wurth_60900213421 23.419,33.151 r90 top
SH-J16 "60900213421" Wurth_60900213421 20.864,33.151 r90 top
SH-J17 "60900213421" Wurth_60900213421 18.309,33.151 r90 top
SH-J18 "60900213421" Wurth_60900213421 15.754,33.151 r90 top
SH-J19 "60900213421" Wurth_60900213421 13.199,33.151 r90 top
SH-J20 "60900213421" Wurth_60900213421 10.644,33.151 r90 top
SH-J21 "60900213421" Wurth_60900213421 74.431,33.823 r90 top
TP1 "TESTPOINT" TP_SM_1MM 19.878,15.153 r180 bottom
TP2 "TESTPOINT" TP_SM_1MM 22.071,15.153 r180 bottom
TP3 "TESTPOINT" TP_SM_1MM 24.264,15.153 r180 bottom
TP4 "TESTPOINT" TP_SM_1MM 26.457,15.153 r180 bottom
TP5 "TESTPOINT" TP_SM_1MM 28.65,15.153 r180 bottom
TP6 "TESTPOINT" TP_SM_1MM 30.843,15.153 r180 bottom
TP7 "TESTPOINT" TP_SM_1MM 33.036,15.153 r180 bottom
TP8 "5002" Keystone5002 41.377,30.328 r90 top
TP9 "5012" Keystone5012 54.958,67.41 r90 top
TP10 "5012" Keystone5012 54.958,63.454 r90 top
TP11 "5012" Keystone5012 54.958,59.497 r90 top
TP12 "5012" Keystone5012 54.958,55.541 r90 top
TP13 "5012" Keystone5012 54.958,51.585 r90 top
TP14 "5012" Keystone5012 54.958,47.629 r90 top
TP15 "5012" Keystone5012 54.958,43.673 r90 top
TP16 "5016" Testpoint_Keystone_Compact 69.811,53.849 r0 top
TP17 "5016" Testpoint_Keystone_Compact 69.912,47.289 r180 top
TP18 "5012" Keystone5012 54.958,39.717 r90 top
TP19 "5012" Keystone5012 54.958,35.761 r90 top
TP20 "5010" Keystone5010 118.016,22.472 r0 top
TP21 "5010" Keystone5010 134.112,21.336 r90 top
TP22 "5012" Keystone5012 109.539,37.765 r0 top
TP23 "5012" Keystone5012 87.546,37.765 r0 top
TP24 "5012" Keystone5012 97.647,8.254 r0 top
TP25 "5011" Keystone5011 133.997,47.941 r90 top
TP26 "5011" Keystone5011 122.342,51.187 r0 top
TP27 "5012" Keystone5012 117.211,8.237 r0 top
TP28 "5012" Keystone5012 103.833,37.765 r180 top
TP29 "5012" Keystone5012 95.795,37.765 r0 top
TP30 "TP_H0.45P0.75" TP_H045P075 125.927,47.506 r90 top
TP31 "5012" Keystone5012 76.102,93.243 r0 top
TP32 "5012" Keystone5012 57.455,93.243 r0 top
TP33 "5012" Keystone5012 85.293,93.058 r0 top
TP34 "5012" Keystone5012 79.119,37.765 r0 top
TP35 "5012" Keystone5012 113.614,93.04 r0 top
TP36 "5012" Keystone5012 132.512,93.04 r0 top
TP37 "5012" Keystone5012 71.884,8.508 r0 top
TP38 "5012" Keystone5012 103.988,93.04 r0 top
TP39 "5012" Keystone5012 69.463,37.608 r0 top
TP40 "5012" Keystone5012 137.658,79.728 r0 top
TP41 "5012" Keystone5012 137.658,67.25 r0 top
TP42 "5012" Keystone5012 137.658,54.5 r0 top
TP43 "TP_H0.45P0.75" TP_H045P075 95.114,41.403 r180 top
TP44 "5012" Keystone5012 48.348,8.487 r0 top
TP45 "TP_H0.45P0.75" TP_H045P075 93.545,41.403 r270 top
TP46 "5012" Keystone5012 137.658,84.728 r0 top
TP47 "5012" Keystone5012 137.658,72 r0 top
TP48 "5012" Keystone5012 137.658,59.553 r0 top
TP49 "5012" Keystone5012 40.185,66.253 r0 top
U1 "MSPM0G3507SPM" PM0064A-MFG 22.912,48.514 r270 top
U2 "DRV8003QWRGZRQ1" RGZ0048M-MFG 94.315,48.039 r270 top
U3 "TCAN28473RHBQ1" RHB0032U-MFG 23.32,66.003 r0 top
U4 "ESD2CAN24DBZR" DBZ0003A-MFG 23.406,82.608 r90 top
USB1 "1051640001" Molex_1051640001 -0.08,20.545 r270 top
XDS1 "MSP432E401YTPDTR" PDT0128A 23.307,20.08 r180 top
Y1 "NX3225GA-16.000M-STD-CRG-1" NDK_NX3225GA 12.107,16.939 r180 top
Y2 "X1E0000210179" FP-X1E0000210179_TSX-3225-MFG 28.372,38.818 r180 top
ZZ1 "This Assembly Note is for PCB labels only" AssemblyNoteLabel 1.982,197.104 r0 top
ZZ2 "These assemblies are ESD sensitive, ESD precautions shall be observed." AssemblyNote 2.108,194.107 r0 top
ZZ3 "These assemblies must be clean and free from flux and all contaminants. Use of no clean flux is not acceptable." AssemblyNote 2.083,190.932 r0 top
ZZ4 "These assemblies must comply with workmanship standards IPC-A-610 Class 2, unless otherwise specified." AssemblyNote 2.083,187.249 r0 top

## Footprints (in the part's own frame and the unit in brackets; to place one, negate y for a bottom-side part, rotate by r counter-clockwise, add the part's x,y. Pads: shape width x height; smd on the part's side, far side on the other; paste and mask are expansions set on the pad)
0402 [mm] "0402 from SM-752 data"
  rect 0.8x0.6 smd: 1(-0.6,0) 2(0.6,0)
  silkscreen extent -1.22,-0.52 1.22,0.52, body extent -0.55,-0.3 0.55,0.3, height 0.6
0402S [mil] "Based on C0402S footprint from PADS legacy"
  rect 15x24 smd: 1(-20,0) 2(20,0)
  body extent -22,-12 22,12, height 24
0603 [mm] "0603 from SM-752 data"
  rect 1x0.95 smd: 1(-0.8,0) 2(0.8,0)
  silkscreen extent -1.52,-0.69 1.52,0.69, body extent -0.87,-0.47 0.87,0.47, height 1
0603L [mm] "0603 from SM-752 data"
  rect 0.8x0.85 smd: 1(-0.7,0) 2(0.7,0)
  silkscreen extent -0.07,-0.33 0.07,0.32, body extent -0.87,-0.47 0.87,0.47, height 1
0603S [mil]
  rect 20x35 smd: 1(-30,0) 2(30,0)
  body extent -34,-19 34,19, height 39
0805L [mm] "0805 from SM-752 data"
  rect 1.1x1.4 smd: 1(-0.75,0) 2(0.75,0)
  body extent -1.1,-0.72 1.1,0.72, height 1.45
1206_180 [mm] "1206_180"
  rect 1.1x1.6 smd: 1(-1.7,0) 2(1.7,0)
  silkscreen extent -0.9,-1 0.9,1, body extent -1.75,-0.95 1.75,0.95, height 1.8
2512_084 [mm] "Chip Resistor, Body 6.3x3.2mm"
  rect 1.3x3.4 smd: 1(-2.95,0) 2(2.95,0)
  silkscreen extent -1.9,-1.6 1.9,1.6, body extent -3.22,-1.67 3.22,1.67, height 0.84
ACT45B_NoSilk [mm] "SMD, 4-Leads, Body 4.7 x 3.7 mm"
  rect 1.35x0.9 smd: 1(-2.275,1.25) 2(-2.275,-1.25) 3(2.275,-1.25) 4(2.275,1.25)
  body extent -2.35,-1.7 2.35,1.7, height 3
AssemblyNote [mm] "Assembly Note"
AssemblyNoteLabel [mm] "Assembly Note for PCB Labels"
Bumpon_SJ5003Transparent [mil] "3M Hemispherical Bumpon transparent"
  round 1 on Mech4: 0(0,0)
  silkscreen extent -228,-228 228,228, body extent -218,-218 219,218, height 197
CE_Mark_5mm [mm] "Minimum text height for CE Mark"
  silkscreen extent -3.5,-2.5 3.5,2.5
DBZ0003A-MFG [mm]
  rrect17% 1.3x0.6 smd paste+0 mask+0: 1(-1.05,0.95) 2(-1.05,-0.95) 3(1.05,0)
  silkscreen extent -0.7,-1.52 0.7,1.52, body extent -1.8,-1.62 1.8,1.62, height 0.25
DCK0005A_N [mm] "SOT353, 5-Leads, Body 2x1.3mm, Pitch 0.65mm, Lead Span 2.1mm, IPC Medium Density"
  rrect25% 0.85x0.4 smd: 1(-1.125,0.65) 2(-1.125,0) 3(-1.125,-0.65) 4(1.125,-0.65) 5(1.125,0.65)
  silkscreen extent -1.47,-1.03 0.55,1.1, body extent -1.14,-1 1.14,1, height 0.95
DNK0008A [mm] "SON, 8-Leads, Body 5x6mm"
  rrect39% 0.86x0.51 smd paste-0.05 mask-0.05: 1(-2.82,1.905) 2(-2.82,0.635) 3(-2.82,-0.635) 4(-2.82,-1.905) 5(2.82,-1.905) 6(2.82,-0.635) 7(2.82,0.635) 8(2.82,1.905)
  rrect40% 0.25x0.555 on Top Solder: 9(-0.83,2.372) 9(-0.83,-2.372)
  rrect40% 0.25x0.555 on Top Paste: 9(-0.83,2.372) 9(-0.83,-2.372)
  rrect11% 0.95x1.13 on Top Paste: 9(-0.535,1.33) 9(-0.535,0) 9(-0.535,-1.33) 9(0.615,1.33) 9(0.615,0) 9(0.615,-1.33) 9(1.765,-1.33) 9(1.765,0) 9(1.765,1.33)
  rrect3% 3.58x4 on Top Solder: 9(0.75,0)
  rrect5% 4.34x5.4 smd paste-3 mask-3: 9(1.08,0)
  body extent -3.05,-2.55 3.05,2.55, height 1.06
DQJ0008A [mm] "SMD, 8-Leads, Body 5.75x4.9mm"
  rrect39% 0.91x0.51 smd paste-0.05 mask-0.05: 1(-2.795,1.905) 2(-2.795,0.635) 3(-2.795,-0.635) 4(-2.795,-1.905) 5(2.795,-1.905) 6(2.795,-0.635) 7(2.795,0.635) 8(2.795,1.905)
  rrect8% 1.58x1.25 on Top Paste: 9(-0.38,1.45) 9(-0.38,0) 9(-0.38,-1.45) 9(1.4,-1.45) 9(1.4,0) 9(1.4,1.45)
  rrect3% 3.48x4.47 on Top Solder: 9(0.55,0)
  rrect2% 4.49x4.57 smd paste-2.5 mask-2.5: 9(1.005,0)
  silkscreen extent -3,-2.6 3,2.6, body extent -3.13,-2.45 3.13,2.45, height 1.15
DRB0008A [mm] "VSON-8"
  rrect32% 0.6x0.31 smd: 1(-1.4,0.975) 2(-1.4,0.325) 3(-1.4,-0.325) 4(-1.4,-0.975) 5(1.4,-0.975) 6(1.4,-0.325) 7(1.4,0.325) 8(1.4,0.975)
  rrect7% 1.5x1.75 smd paste-0.75: 9(0,0)
  Top Layer region: -0.7,-0.875 -0.49,-0.875 -0.471,-0.879 -0.455,-0.89 -0.444,-0.906 -0.44,-0.925 -0.44,-0.925 -0.44,-1.65 -0.436,-1.669 -0.425,-1.685 -0.409,-1.696 -0.39,-1.7 -0.39,-1.7 -0.26,-1.7 -0.241,-1.696 -0.225,-1.685 -0.214,-1.669 -0.21,-1.65 -0.21,-1.65 -0.21,-0.925 -0.206,-0.906 -0.195,-0.89 -0.179,-0.879 -0.16,-0.875 -0.16,-0.875 0.16,-0.875 0.179,-0.879 0.195,-0.89 0.206,-0.906 0.21,-0.925 0.21,-0.925 0.21,-1.65 0.21,-1.65 0.214,-1.669 0.225,-1.685 0.241,-1.696 0.26,-1.7 0.26,-1.7 0.39,-1.7 0.409,-1.696 0.425,-1.685 0.436,-1.669 0.44,-1.65 0.44,-1.65 0.44,-0.925 0.444,-0.906 0.455,-0.89 0.471,-0.879 0.49,-0.875 0.49,-0.875 0.7,-0.875 0.719,-0.871 0.735,-0.86 0.746,-0.844 0.75,-0.825 0.75,-0.825 0.75,0.825 0.746,0.844 0.735,0.86 0.719,0.871 0.7,0.875 0.7,0.875 0.49,0.875 0.471,0.879 0.455,0.89 0.444,0.906 0.44,0.925 0.44,0.925 0.44,1.65 0.436,1.669 0.425,1.685 0.409,1.696 0.39,1.7 0.39,1.7 0.26,1.7 0.241,1.696 0.225,1.685 0.214,1.669 0.21,1.65 0.21,1.65 0.21,1.65 0.21,0.925 0.206,0.906 0.195,0.89 0.179,0.879 0.16,0.875 0.16,0.875 -0.16,0.875 -0.179,0.879 -0.195,0.89 -0.206,0.906 -0.21,0.925 -0.21,0.925 -0.21,1.65 -0.214,1.669 -0.225,1.685 -0.241,1.696 -0.26,1.7 -0.26,1.7 -0.39,1.7 -0.409,1.696 -0.425,1.685 -0.436,1.669 -0.44,1.65 -0.44,1.65 -0.44,0.925 -0.444,0.906 -0.455,0.89 -0.471,0.879 -0.49,0.875 -0.49,0.875 -0.7,0.875 -0.719,0.871 -0.735,0.86 -0.746,0.844 -0.75,0.825 -0.75,0.825 -0.75,-0.825 -0.746,-0.844 -0.735,-0.86 -0.719,-0.871 -0.7,-0.875
  silkscreen extent -1.72,-1.73 1.72,1.73, body extent -1.5,-1.5 1.5,1.5, height 0.77
DRY0006A [mm] "USON-6"
  rrect67% 0.45x0.3 smd paste-0.05 mask-0.05: 1(-0.275,0.5)
  rrect67% 0.4x0.3 smd paste-0.05 mask-0.05: 2(-0.3,0) 3(-0.3,-0.5) 4(0.3,-0.5) 5(0.3,0) 6(0.3,0.5)
  body extent -0.5,-0.72 0.5,0.73, height 0.58
DYF0002A-MFG [mm]
  rrect20% 0.9x0.5 smd paste+0 mask+0: 1(-1.3,0) 2(1.3,0)
  silkscreen extent -1.55,-0.7 0.9,0.92, body extent -1.85,-0.8 1.85,0.8, height 0.25
FCC_disclaimer [mm]
Fiducial10-20 [mm]
  round 1 smd mask+0.5: 1(0,0)
  Top Layer keep-out circle w1.178: c0,0 r0.5
FP-74439369022_IND_SMT_11MM6_10MM5-MFG [mil]
  round 1 smd paste+0 mask+0: 1(-72,125.98) 2(-72,-125.99)
  Top Layer region: -25.16,-76.77 -25.16,-154.54 15.54,-154.54 15.54,-76.77 177.15,-76.77 177.15,-124.78 177.16,-125.38 177.17,-125.99 177.17,-125.99 177.17,-175.2 -177.17,-175.2 -177.15,-127.19 -177.15,-76.77
  Top Layer region: -25.16,76.77 -25.16,153.28 14.97,153.28 14.97,76.77 175.2,76.77 175.95,76.92 176.59,77.35 177.02,77.99 177.17,78.74 177.17,78.74 177.17,173.23 177.02,173.98 176.59,174.62 175.95,175.05 175.2,175.2 175.2,175.2 -175.2,175.2 -175.95,175.05 -176.59,174.62 -177.02,173.98 -177.17,173.23 -177.17,173.23 -177.17,78.74 -177.02,77.99 -176.59,77.35 -175.95,76.92 -175.2,76.77 -175.2,76.77
  body extent -238,-217 238,217, height 10
FP-430481025816_SMT_SW_6MM2_6MM2-MFG [mm]
  rrect7% 2x1.4 smd paste+0 mask+0: 1(-3.5,2) 2(3.5,2) 3(-3.5,-2) 4(3.5,-2)
  silkscreen extent -5.17,-3.2 3.2,3.2, body extent -4.6,-3.3 4.6,3.3, height 0.25
FP-691216710002_HDR2-MFG [mm]
  rrect4% 2.3x2.3 hole 1.5 paste-2539.97 mask+0: 1(-2.8,-0.3)
  round 2.3 hole 1.5 paste-2539.97 mask+0: 2(2.2,-0.3)
  silkscreen extent -6.3,-4.95 5,4.95, body extent -5.6,-5.05 5.6,5.05, height 0.25
FP-691250610002_CONN_TERM_BLOCK2-MFG [mm]
  rrect4% 2.3x2.3 hole 1.5 paste-2539.97 mask+0: 1(-2.875,1.65)
  round 2.3 hole 1.5 paste-2539.97 mask+0: 2(3.475,1.65)
  silkscreen extent -7.52,-6.3 6.85,6.3, body extent -6.95,-6.4 6.95,6.4, height 0.25
FP-691256610002_HDR2-MFG [mm]
  rrect4% 2.45x2.45 hole 1.6 paste-2539.97 mask+0: 1(-5.08,7.55)
  round 2.45 hole 1.6 paste-2539.97 mask+0: 1(-5.08,-2.61) 2(5.08,7.55) 2(5.08,-2.61)
  silkscreen extent -11,-9.2 10.21,9.2, body extent -10.31,-9.3 10.31,9.3, height 0.25
FP-860020675021_RADIAL-MFG [mm]
  rrect7% 1.4x1.4 hole 0.9 paste-2539.97 mask+0: 1(-2.5,0)
  round 1.4 hole 0.9 paste-2539.97 mask+0: 2(2.5,0)
  silkscreen extent -5.25,-5.25 5.25,5.25, body extent -5.35,-5.35 5.35,5.35, height 0.25
FP-885012206090_0603-MFG [mm]
  rrect13% 0.8x0.8 smd paste+0 mask+0: 1(-0.75,0) 2(0.75,0)
  body extent -1.25,-0.55 1.25,0.55, height 0.25
FP-B340AE-13_SMA-MFG [mm] "Recommended Land Pattern"
  rrect6% 2.5x1.7 smd paste+0 mask+0: 1(-2,0) 2(2,0)
  silkscreen extent -3.92,-1.46 2.3,1.46, body extent -2.6,-1.3 2.6,1.3, height 2.4
FP-X1E0000210179_TSX-3225-MFG [mm]
  rrect9% 1.4x1.15 smd paste+0 mask+0: 1(-1.1,-0.8) 2(1.1,-0.8) 3(1.1,0.8) 4(-1.1,0.8)
  silkscreen extent -1.22,-2.05 0,1.33, body extent -1.6,-1.25 1.6,1.25, height 0.6
Fuse_0463 [mm] "SMD, 2-Leads, Body 10.1x3.12mm"
  rrect3% 3.25x3.43 smd: 1(-4.675,0) 2(4.675,0)
  silkscreen extent -2.6,-1.5 2.6,1.5, body extent -5.05,-1.56 5.05,1.56, height 3.12
Harwin_D3082-05 [mm] "Shorting Plug, 10.16mm spacing, TH"
  round 1.8 hole 1.3: 1(-5.08,0) 2(5.08,0)
  silkscreen extent -3.9,-0.53 3.9,0.52, body extent -5.6,-0.52 5.61,0.52, height 6.63
IEC_Caution_Small [mm]
  silkscreen extent -2.72,-2.36 2.72,2.35
IEC_HotSurface_Small [mm]
  silkscreen extent -2.72,-2.36 2.72,2.35
Keystone5002 [mil] "For Keystone 500x miniature loop terminals"
  round 80 hole 40: 1(0,0)
  silkscreen extent -52,-52 52,52, body extent -49,-49 49,49, height 182
Keystone5010 [mil] "Keystone Multipurpose loops"
  round 87 hole 63: 1(0,0)
  silkscreen extent -70,-70 70,70, body extent -63,-63 63,62, height 319
Keystone5011 [mil] "Keystone Multipurpose loops"
  round 87 hole 63: 1(0,0)
  silkscreen extent -70,-70 70,70, body extent -63,-63 63,62, height 319
Keystone5012 [mil] "Keystone Multipurpose loops"
  round 87 hole 63: 1(0,0)
  silkscreen extent -70,-70 70,70, body extent -63,-63 63,62, height 319
LED_LTST-C190 [mm] "Lite-On"
  rect 0.8x0.8 smd: 1(-0.75,0) 2(0.75,0)
  silkscreen extent -1.1,-0.8 1.8,0.8, body extent -0.85,-0.45 0.85,0.45, height 0.9
LED_LTST-C190_Red [mm] "Lite-On"
  rect 0.8x0.8 smd: 1(-0.75,0) 2(0.75,0)
  silkscreen extent -1.1,-0.8 1.8,0.8, body extent -0.85,-0.45 0.85,0.45, height 0.9
Molex_1051640001 [mm] "Receptacle, USB 2.0, Micro B, 5 Pos, 0.65mm Pitch, R/A, SMT"
  rrect22% 0.45x1.38 smd: 1(1.3,4.11) 2(0.65,4.11) 3(0,4.11) 4(-0.65,4.11) 5(-1.3,4.11)
  rrect7% 1.475x2.1 smd: 6(-2.462,3.75) 11(2.462,3.75)
  rrect100% 1.524x1.905 hole 0.6 slot 1.3 at 90 deg: 7(-3.95,1.45) 10(3.95,1.45)
  rrect20% 1.375x1.9 smd: 8(-0.938,1.45) 9(0.938,1.45)
  silkscreen extent 1.2,5.1 1.4,5.4, body extent -4.1,-0.7 4.1,4.47, height 2.45
NDK_NX3225GA [mm] "NDK"
  rect 1.2x1.4 smd: 1(-0.8,1.1) 2(-0.8,-1.1) 3(0.8,-1.1) 4(0.8,1.1)
  silkscreen extent -1.9,-0.1 1.4,2, body extent -1.3,-1.65 1.3,1.65, height 0.9
NORCOMP_190-009-263R001 [mil] "Norcomp"
  rect 32x146 smd: 1(-218,-105) 2(-109,-105.2) 3(0,-105.2) 4(109,-105.2) 5(218,-105.2) 6(-163.5,-105.2) 7(-54.5,-105.2) 8(54.5,-105.2) 9(163.5,-105.2)
  round 170 hole 120: 10(-492,-110) 11(492,-110)
  round 40 hole 59 unplated: MH(-313,-110) MH(313,-110)
  silkscreen extent -620,-160 630,-95, body extent -593,-138 592,280, height 425
PDT0128A [mm] "Thin QFP, 128-Leads, Body 14x14mm, Pitch 0.4mm"
  oval 1.4x0.2 smd: 1(-7.7,6.2) 2(-7.7,5.8) 3(-7.7,5.4) 4(-7.7,5) 5(-7.7,4.6) 6(-7.7,4.2) 7(-7.7,3.8) 8(-7.7,3.4) 9(-7.7,3) 10(-7.7,2.6) 11(-7.7,2.2) 12(-7.7,1.8) 13(-7.7,1.4) 14(-7.7,1) 15(-7.7,0.6) 16(-7.7,0.2) 17(-7.7,-0.2) 18(-7.7,-0.6) 19(-7.7,-1) 20(-7.7,-1.4) 21(-7.7,-1.8) 22(-7.7,-2.2) 23(-7.7,-2.6) 24(-7.7,-3) 25(-7.7,-3.4) 26(-7.7,-3.8) 27(-7.7,-4.2) 28(-7.7,-4.6) 29(-7.7,-5) 30(-7.7,-5.4) 31(-7.7,-5.8) 32(-7.7,-6.2) 65(7.7,-6.2) 66(7.7,-5.8) 67(7.7,-5.4) 68(7.7,-5) 69(7.7,-4.6) 70(7.7,-4.2) 71(7.7,-3.8) 72(7.7,-3.4) 73(7.7,-3) 74(7.7,-2.6) 75(7.7,-2.2) 76(7.7,-1.8) 77(7.7,-1.4) 78(7.7,-1) 79(7.7,-0.6) 80(7.7,-0.2) 81(7.7,0.2) 82(7.7,0.6) 83(7.7,1) 84(7.7,1.4) 85(7.7,1.8) 86(7.7,2.2) 87(7.7,2.6) 88(7.7,3) 89(7.7,3.4) 90(7.7,3.8) 91(7.7,4.2) 92(7.7,4.6) 93(7.7,5) 94(7.7,5.4) 95(7.7,5.8) 96(7.7,6.2)
  oval 0.2x1.4 smd: 33(-6.2,-7.7) 34(-5.8,-7.7) 35(-5.4,-7.7) 36(-5,-7.7) 37(-4.6,-7.7) 38(-4.2,-7.7) 39(-3.8,-7.7) 40(-3.4,-7.7) 41(-3,-7.7) 42(-2.6,-7.7) 43(-2.2,-7.7) 44(-1.8,-7.7) 45(-1.4,-7.7) 46(-1,-7.7) 47(-0.6,-7.7) 48(-0.2,-7.7) 49(0.2,-7.7) 50(0.6,-7.7) 51(1,-7.7) 52(1.4,-7.7) 53(1.8,-7.7) 54(2.2,-7.7) 55(2.6,-7.7) 56(3,-7.7) 57(3.4,-7.7) 58(3.8,-7.7) 59(4.2,-7.7) 60(4.6,-7.7) 61(5,-7.7) 62(5.4,-7.7) 63(5.8,-7.7) 64(6.2,-7.7) 97(6.2,7.7) 98(5.8,7.7) 99(5.4,7.7) 100(5,7.7) 101(4.6,7.7) 102(4.2,7.7) 103(3.8,7.7) 104(3.4,7.7) 105(3,7.7) 106(2.6,7.7) 107(2.2,7.7) 108(1.8,7.7) 109(1.4,7.7) 110(1,7.7) 111(0.6,7.7) 112(0.2,7.7) 113(-0.2,7.7) 114(-0.6,7.7) 115(-1,7.7) 116(-1.4,7.7) 117(-1.8,7.7) 118(-2.2,7.7) 119(-2.6,7.7) 120(-3,7.7) 121(-3.4,7.7) 122(-3.8,7.7) 123(-4.2,7.7) 124(-4.6,7.7) 125(-5,7.7) 126(-5.4,7.7) 127(-5.8,7.7) 128(-6.2,7.7)
  silkscreen extent -7.7,-6.3 6.3,6.99, body extent -8,-8 8,8, height 1.07
PM0064A-MFG [mm]
  rrect33% 1.5x0.3 smd paste+0 mask+0: 1(-5.7,3.75) 2(-5.7,3.25) 3(-5.7,2.75) 4(-5.7,2.25) 5(-5.7,1.75) 6(-5.7,1.25) 7(-5.7,0.75) 8(-5.7,0.25) 9(-5.7,-0.25) 10(-5.7,-0.75) 11(-5.7,-1.25) 12(-5.7,-1.75) 13(-5.7,-2.25) 14(-5.7,-2.75) 15(-5.7,-3.25) 16(-5.7,-3.75) 33(5.7,-3.75) 34(5.7,-3.25) 35(5.7,-2.75) 36(5.7,-2.25) 37(5.7,-1.75) 38(5.7,-1.25) 39(5.7,-0.75) 40(5.7,-0.25) 41(5.7,0.25) 42(5.7,0.75) 43(5.7,1.25) 44(5.7,1.75) 45(5.7,2.25) 46(5.7,2.75) 47(5.7,3.25) 48(5.7,3.75)
  rrect33% 0.3x1.5 smd paste+0 mask+0: 17(-3.75,-5.7) 18(-3.25,-5.7) 19(-2.75,-5.7) 20(-2.25,-5.7) 21(-1.75,-5.7) 22(-1.25,-5.7) 23(-0.75,-5.7) 24(-0.25,-5.7) 25(0.25,-5.7) 26(0.75,-5.7) 27(1.25,-5.7) 28(1.75,-5.7) 29(2.25,-5.7) 30(2.75,-5.7) 31(3.25,-5.7) 32(3.75,-5.7) 49(3.75,5.7) 50(3.25,5.7) 51(2.75,5.7) 52(2.25,5.7) 53(1.75,5.7) 54(1.25,5.7) 55(0.75,5.7) 56(0.25,5.7) 57(-0.25,5.7) 58(-0.75,5.7) 59(-1.25,5.7) 60(-1.75,5.7) 61(-2.25,5.7) 62(-2.75,5.7) 63(-3.25,5.7) 64(-3.75,5.7)
  silkscreen extent -7.12,-5.1 5.1,5.1, body extent -6.55,-6.55 6.55,6.55, height 0.25
RGZ0048M-MFG [mm] "Recommended Land Pattern"
  rrect40% 0.6x0.25 smd paste+0 mask+0: 1(-3.4,2.75) 2(-3.4,2.25) 3(-3.4,1.75) 4(-3.4,1.25) 5(-3.4,0.75) 6(-3.4,0.25) 7(-3.4,-0.25) 8(-3.4,-0.75) 9(-3.4,-1.25) 10(-3.4,-1.75) 11(-3.4,-2.25) 12(-3.4,-2.75) 25(3.4,-2.75) 26(3.4,-2.25) 27(3.4,-1.75) 28(3.4,-1.25) 29(3.4,-0.75) 30(3.4,-0.25) 31(3.4,0.25) 32(3.4,0.75) 33(3.4,1.25) 34(3.4,1.75) 35(3.4,2.25) 36(3.4,2.75)
  rrect40% 0.25x0.6 smd paste+0 mask+0: 13(-2.75,-3.4) 14(-2.25,-3.4) 15(-1.75,-3.4) 16(-1.25,-3.4) 17(-0.75,-3.4) 18(-0.25,-3.4) 19(0.25,-3.4) 20(0.75,-3.4) 21(1.25,-3.4) 22(1.75,-3.4) 23(2.25,-3.4) 24(2.75,-3.4) 37(2.75,3.4) 38(2.25,3.4) 39(1.75,3.4) 40(1.25,3.4) 41(0.75,3.4) 42(0.25,3.4) 43(-0.25,3.4) 44(-0.75,3.4) 45(-1.25,3.4) 46(-1.75,3.4) 47(-2.25,3.4) 48(-2.75,3.4)
  rrect2% 5.6x5.6 smd paste-1000 mask+0: 49(0,0)
  silkscreen extent -4.37,-3.55 3.55,3.55, body extent -3.51,-3.51 3.51,3.51, height 1
RHB0032U-MFG [mm]
  rrect40% 0.6x0.25 smd paste+0 mask+0: 1(-2.4,1.75) 2(-2.4,1.25) 3(-2.4,0.75) 4(-2.4,0.25) 5(-2.4,-0.25) 6(-2.4,-0.75) 7(-2.4,-1.25) 8(-2.4,-1.75) 17(2.4,-1.75) 18(2.4,-1.25) 19(2.4,-0.75) 20(2.4,-0.25) 21(2.4,0.25) 22(2.4,0.75) 23(2.4,1.25) 24(2.4,1.75)
  rrect40% 0.25x0.6 smd paste+0 mask+0: 9(-1.75,-2.4) 10(-1.25,-2.4) 11(-0.75,-2.4) 12(-0.25,-2.4) 13(0.25,-2.4) 14(0.75,-2.4) 15(1.25,-2.4) 16(1.75,-2.4) 25(1.75,2.4) 26(1.25,2.4) 27(0.75,2.4) 28(0.25,2.4) 29(-0.25,2.4) 30(-0.75,2.4) 31(-1.25,2.4) 32(-1.75,2.4)
  rrect3% 3.7x3.7 smd paste-1000 mask+0: 33(0,0)
  silkscreen extent -3.37,-2.55 2.55,2.55, body extent -2.8,-2.8 2.8,2.8, height 0.25
Samtec_TSW-112-08-x-D [mm] "Header, 2.54mm, 12x2, TH"
  rrect50% 1.53x1.53 hole 1.02: 1(-1.27,13.97)
  round 1.53 hole 1.02: 2(1.27,13.97) 3(-1.27,11.43) 4(1.27,11.43) 5(-1.27,8.89) 6(1.27,8.89) 7(-1.27,6.35) 8(1.27,6.35) 9(-1.27,3.81) 10(1.27,3.81) 11(-1.27,1.27) 12(1.27,1.27) 13(-1.27,-1.27) 14(1.27,-1.27) 15(-1.27,-3.81) 16(1.27,-3.81) 17(-1.27,-6.35) 18(1.27,-6.35) 19(-1.27,-8.89) 20(1.27,-8.89) 21(-1.27,-11.43) 22(1.27,-11.43) 23(-1.27,-13.97) 24(1.27,-13.97)
  body extent -2.54,-15.24 2.54,15.24, height 8.38
SOD-123 [mm] "On Semi recommended land pattern"
  rect 0.915x1.22 smd: 1(-1.638,0) 2(1.638,0)
  silkscreen extent -2.74,-1.17 2.03,1.17, body extent -1.93,-0.9 1.93,0.9, height 1.35
SOD-323 [mm] "NXP recommended land pattern"
  rect 0.6x0.6 smd paste-0.05: 1(-1.1,0) 2(1.1,0)
  silkscreen extent -2.06,-0.86 1.53,0.86, body extent -1.3,-0.67 1.3,0.68, height 1.1
SOT-23L [mm] "SOT23, 3-Leads, Body 2.9x1.3mm, Pitch 0.95mm, Lead Span 2.5mm, IPC High Density"
  rrect50% 0.8x0.6 smd: 1(-1.1,0.95) 2(-1.1,-0.95) 3(1.1,0)
  silkscreen extent -1.5,-1.5 0.7,1.5, body extent -1.16,-1.45 1.21,1.45, height 1
Testpoint_Keystone_Compact [mil] "Compact SMT test point"
  rect 185x135 smd: 1(0,0)
  silkscreen extent -110,-80 110,80, body extent -75,-56 75,56, height 91
TI_Stacked_Overlay_Small [mm]
  silkscreen extent -10.63,-2.49 10.63,2.49
TP_H045P075 [mm] "TP_H0.45P0.75"
  round 0.75 hole 0.45: 1(0,0)
TP_SM_1MM [mm] "1mm Test Point, SMT"
  round 1 smd paste-0.5: 1(0,0)
TSW-102-07-G-S [mm] "Samtec 100mil, 1x2, 230 mil above insulator"
  rrect50% 1.65x1.65 hole 1.016: 1(-1.27,0)
  round 1.65 hole 1.016: 2(1.27,0)
  silkscreen extent -3.17,-1.27 2.54,1.27, body extent -2.54,-1.27 2.54,1.27, height 8.38
TSW-103-07-G-S [mm] "Samtec 100mil, 1x3, 230 mil above insulator"
  rrect50% 1.65x1.65 hole 1.016: 1(-2.54,0)
  round 1.65 hole 1.016: 2(0,0) 3(2.54,0)
  body extent -3.81,-1.27 3.81,1.27, height 8.38
TSW-106-07-G-S [mm] "Samtec 100mil, 1x6, 230 mil above insulator"
  rrect50% 1.65x1.65 hole 1.016: 1(-6.35,0)
  round 1.65 hole 1.016: 2(-3.81,0) 3(-1.27,0) 4(1.27,0) 5(3.81,0) 6(6.35,0)
  body extent -7.62,-1.27 7.62,1.27, height 8.38
TSW-107-07-X-D [mm] "Samtec 100mil, 2x7, 230 mil above insulator"
  rrect6% 1.65x1.65 hole 1.016: 1(-7.62,-1.27)
  round 1.65 hole 1.016: 2(-7.62,1.27) 3(-5.08,-1.27) 4(-5.08,1.27) 5(-2.54,-1.27) 6(-2.54,1.27) 7(0,-1.27) 8(0,1.27) 9(2.54,-1.27) 10(2.54,1.27) 11(5.08,-1.27) 12(5.08,1.27) 13(7.62,-1.27) 14(7.62,1.27)
  silkscreen extent -9.91,-2.52 9.14,2.5, body extent -8.89,-2.54 8.89,2.54, height 8.38
WCAP-ATG5_D10H12.5 [mm] "Aluminum Electrolytic Capacitors, 10x12.5mm"
  rrect50% 1.4x1.4 hole 0.9: 1(2.5,0)
  round 1.4 hole 0.9: 2(-2.5,0)
  silkscreen extent -5.25,-5.25 5.25,5.25, body extent -4.99,-5 5,5, height 12.81
WCAP-CSGP_0402_L1W0.5H0.5 [mm] "Ceramic Capacitors, body 1x0.5mm"
  rect 0.5x0.5 smd: 1(-0.5,0) 2(0.5,0)
  body extent -0.5,-0.25 0.5,0.25, height 0.5
WCAP-CSGP_0603_L1.6W0.8H0.8_Reflow [mm] "Ceramic Capacitors, body 1.6x0.8mm"
  rect 0.8x0.8 smd: 1(-0.75,0) 2(0.75,0)
  body extent -0.8,-0.4 0.8,0.4, height 0.8
WEEE_Minimum [mm] "WEEElie bin"
  silkscreen extent -2.42,-4.38 2.52,2.65
WL-SMCW_GREEN [mm] "WURTH"
  rect 0.8x0.8 smd: 1(-0.8,0) 2(0.8,0)
  silkscreen extent -1.9,-0.8 1.2,0.8, body extent -0.85,-0.45 0.85,0.45, height 0.8
WL-SMCW_RED [mm] "WURTH"
  rect 0.8x0.8 smd: 1(-0.8,0) 2(0.8,0)
  silkscreen extent -1.9,-0.8 1.2,0.8, body extent -0.85,-0.45 0.85,0.45, height 0.8
WSHM2818 [mm] "SMD, 2-Leads, Body 7.1x4.6mm"
  rect 3.5x5.1 smd: 1(-2.055,0) 2(2.055,0)
  body extent -3.55,-2.3 3.55,2.3, height 1.5
Wurth_60900213421 [mil] "Shunt, 2.54mm, Black"
  round 1 on Mech3: 0(0,0)
  body extent -98,-48 98,48, height 338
